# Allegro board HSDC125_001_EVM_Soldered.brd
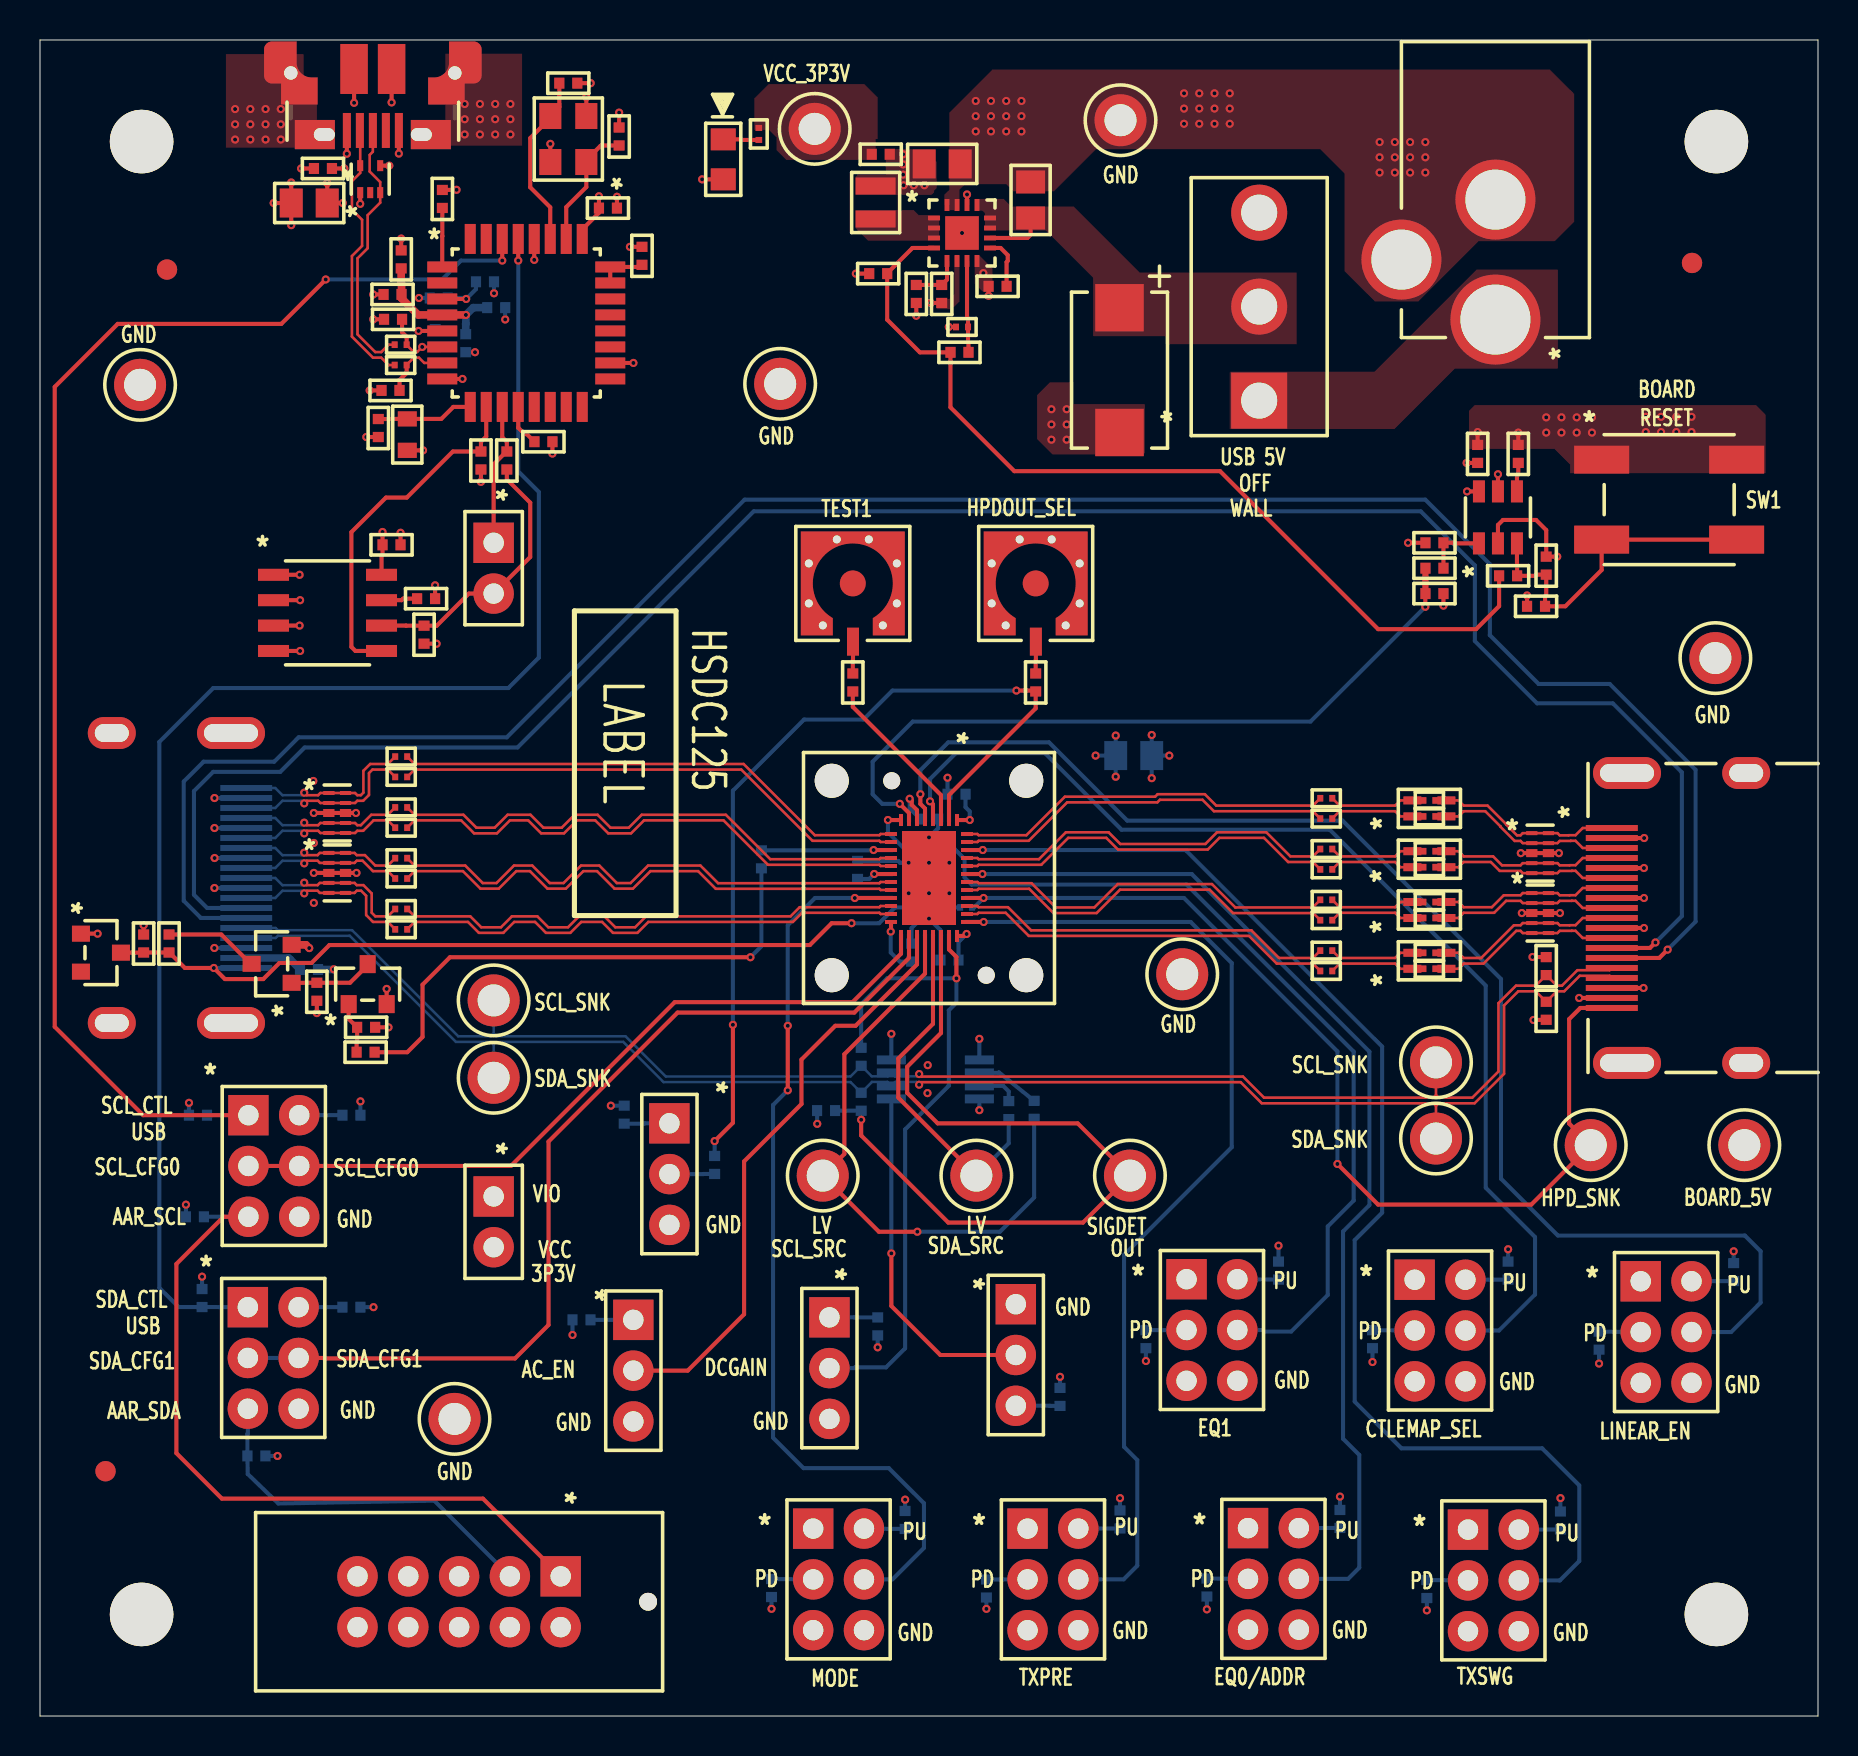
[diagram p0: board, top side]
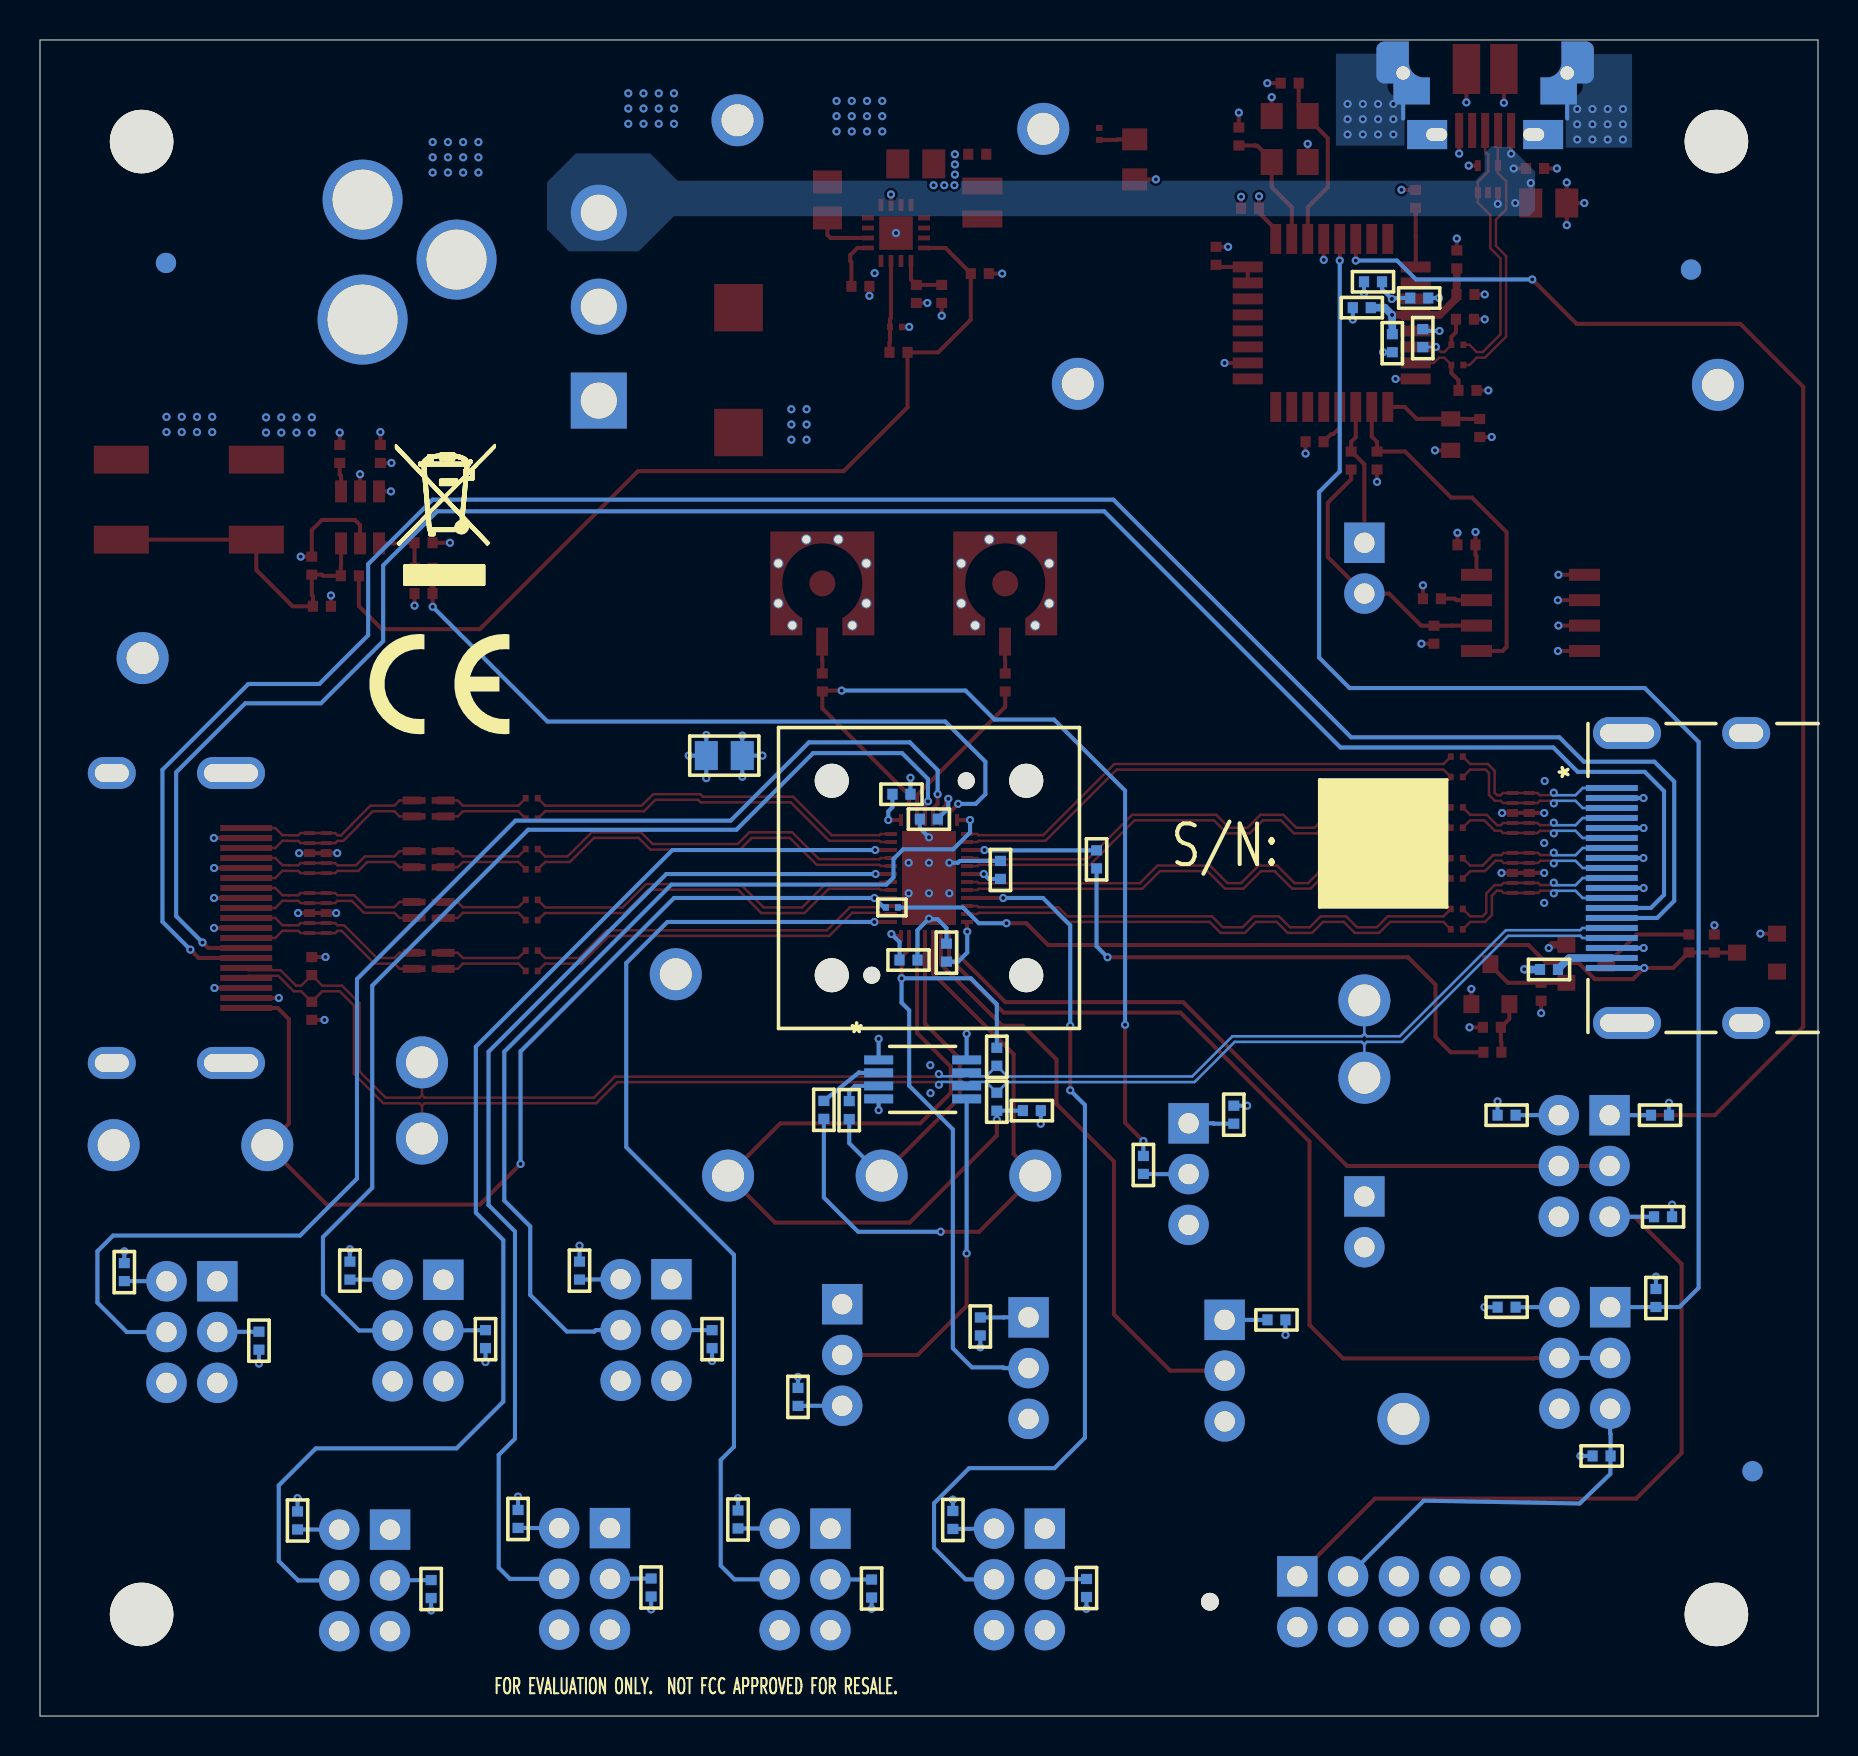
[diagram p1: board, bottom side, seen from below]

Outline 88.9 x 83.82 mm; copper layers: TOP, L2, L3, L4, L5, BOTTOM. Coordinates in mm from the lower left corner of the outline.
Outline path: 0,83.82 88.9,83.82 88.9,0 0,0 0,83.82

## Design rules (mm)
constraint set DEFAULT: min track width 0.203
net group DIFFPAIR0: nets N17024118 N17024121
net group DIFFPAIR1: nets N16919318 N16919400
net group DIFFPAIR2: nets IN_D2N IN_D2P
net group DIFFPAIR3: nets IN_D1N IN_D1P
net group DIFFPAIR4: nets IN_D0N IN_D0P
net group DIFFPAIR5: nets IN_CLKN IN_CLKP
net group DIFFPAIR6: nets IN_D2N_R IN_D2P_R
net group DIFFPAIR7: nets IN_D1N_R IN_D1P_R
net group DIFFPAIR8: nets IN_D0N_R IN_D0P_R
net group DIFFPAIR9: nets IN_CLKN_R IN_CLKP_R
net group DIFFPAIR10: nets OUT_D2N OUT_D2P
net group DIFFPAIR11: nets OUT_D1N OUT_D1P
net group DIFFPAIR12: nets OUT_D0N OUT_D0P
net group DIFFPAIR13: nets OUT_CLKN OUT_CLKP
net group DIFFPAIR14: nets N17100724 N17100737
net group DIFFPAIR15: nets N17100678 N17100691
net group DIFFPAIR16: nets N17100618 N17100645
net group DIFFPAIR17: nets N17100772 N17100781
net group DIFFPAIR18: nets OUTD2N_C OUTD2P_C
net group DIFFPAIR19: nets OUTD1N_C OUTD1P_C
net group DIFFPAIR20: nets OUTD0N_C OUTD0P_C
net group DIFFPAIR21: nets OUTCLKN_C OUTCLKP_C
net group DIFFPAIR22: nets SCL_SNK SDA_SNK
net group DIFF_PAIR 100 OHM_PH: nets EN SCL_CFG0 SCL_CTL_USB SDA_CFG1 SDA_CTL_USB

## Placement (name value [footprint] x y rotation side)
C17  10uF  [CAP_0805]  54.69 48.03 180 bottom
C20  0.1uF  [CAP_0402]  45.47 37.81 180 bottom
C21  0.1uF  [CAP_0402]  44.46 44.85 0 bottom
C22  0.1uF  [CAP_0402]  45.83 46.1 180 bottom
C23  0.1uF  [CAP_0402]  43.58 38.18 90 bottom
C26  DNI - 200nF  [CAP_0402]  69.72 56.13 0 top
C27  18pF  [CAP_0402]  75.31 57.53 90 top
C28  220pF  [CAP_0402]  73.91 63.12 90 top
C29  0.1uF  [CAP_0402]  71.88 63.12 90 top
C30  220uF  [TANT_7343-31]  53.98 67.31 270 top
C31  10uF  [CAP_0805]  49.53 75.82 90 top
C32  22uF  [CAP_0805]  45.11 77.62 0 top
C34  3.3nF  [CAP_0402]  47.88 71.5 180 top
C39  2.2uF  [CAP_0805]  13.46 75.67 180 top
C40  0.1uF  [CAP_0402]  28.4 75.41 180 top
C41  0.01uF  [CAP_0402]  22.25 71.73 180 bottom
C42  0.01uF  [CAP_0402]  19.94 70.92 0 bottom
C45  22pF  [CAP_0402]  17.65 69.85 180 top
C46  0.1uF  [CAP_0402]  21.29 68.66 90 bottom
C47  0.01uF  [CAP_0402]  22.81 70.43 180 bottom
C49  22pF  [CAP_0402]  17.53 66.29 0 top
C50  33pF  [CAP_0402]  28.96 78.99 90 top
C51  33pF  [CAP_0402]  26.42 81.66 0 top
C52  1uF  [CAP_0603]  18.36 64.08 90 top
C59  0.1uF  [CAP_0402]  17.58 58.57 180 top
C60  0.1uF  [CAP_0402]  14.15 77.39 180 top
C61  0.1uF  [CAP_0402]  40.64 51.69 270 top
C63  0.01uF  [CAP_0402]  40.88 42.31 90 bottom
C64  0.1uF  [CAP_0402]  49.78 51.69 270 top
D1  LED Green 0805  [LED_SM_LTST-C171]  34.16 77.85 270 top
D2  Zener 6V  [SOT-23_123]  3.05 38.18 270 top
J5  Header 5x2 0.1" thru-hole  [CON_SHRD_THVT_N2510-6002-XX]  20.95 5.71 270 top
J9  2.1mm x 5.5mm  [JACK_THRT_PJ-202AH]  72.77 69.84 90 top
J13  USB Micro B  [USB-UB_SMRT_10103592]  16.64 81.75 180 top
J18  SMP  [CON_SMVT_19S101-40ML5_R04350]  40.64 56.64 0 top
J25  HDR3X1 M .1  [HDR_THVT_1X3_254_1097]  31.47 27.1 270 top
J27  HDR3X1 M .1  [HDR_THVT_1X3_254_1097]  29.67 17.27 270 top
J30  SMP  [CON_SMVT_19S101-40ML5_R04350]  49.78 56.64 0 top
J31  HDR3X1 M .1  [HDR_THVT_1X3_254_1097]  48.79 18.05 270 top
J32  HEADER 2  [HDR_THVT_1X2_254_820]  22.68 25.98 270 top
J33  HDR3X1 M .1  [HDR_THVT_1X3_254_1097]  39.47 17.4 270 top
JMP4  HEADER 3X2  [HDR_THVT_2X3_254_1097]  38.66 9.37 0 top
JMP5  HEADER 3X2  [HDR_THVT_2X3_254_1097]  68.73 21.82 0 top
JMP6  HEADER 3X2  [HDR_THVT_2X3_254_1097]  57.33 21.84 0 top
JMP7  HEADER 3X2  [HDR_THVT_2X3_254_1097]  49.38 9.37 0 top
JMP8  HEADER 3X2  [HDR_THVT_2X3_254_1097]  60.4 9.4 0 top
JMP9  HEADER 3X2  [HDR_THVT_2X3_254_1097]  71.4 9.32 0 top
JMP13  HEADER 3X2  [HDR_THVT_2X3_254_1097]  80.04 21.74 0 top
JMP15  HEADER 3X2  [HDR_THVT_2X3_254_1097]  10.42 30.05 0 top
JMP16  HEADER 3X2  [HDR_THVT_2X3_254_1097]  10.39 20.45 0 top
JP1  JUMPER  [HDR_THVT_1X2_254_820]  22.68 58.67 270 top
L1  2.2 uH  [IND_SM_VLS252010]  41.78 75.69 90 top
L3  DLM0QSB120HY2B  [IND_SM_4_DLW21S_H]  69.47 42.85 90 top
L4  DLM0QSB120HY2B  [IND_SM_4_DLW21S_H]  69.47 45.39 90 top
L5  DLM0QSB120HY2B  [IND_SM_4_DLW21S_H]  69.47 37.77 90 top
L7  DLM0QSB120HY2B  [IND_SM_4_DLW21S_H]  69.47 40.31 90 top
NOREF  -  [unnamed]  5.08 5.08 0 top
NOREF#2  -  [unnamed]  82.6 72.67 0 top
NOREF#3  -  [unnamed]  6.35 72.34 0 top
NOREF#4  -  [#2]  0 0 0 top
NOREF#5  -  [unnamed]  83.82 5.08 0 top
NOREF#6  -  [#2]  56.16 48.51 0 top
NOREF#7  -  [unnamed]  5.08 78.74 0 top
NOREF#8  -  [#2]  67.03 2.08 0 top
NOREF#9  -  [unnamed]  3.28 12.24 0 top
NOREF#10  -  [unnamed]  83.82 78.74 0 top
NOREF#11  -  [#2]  -3.81 -69.85 0 top
NOREF#12  -  [#2]  88.9 38.1 0 top
NOREF#13  -  [#2]  68.93 51.61 180 bottom
NOREF#14  -  [unnamed]  6.35 72.34 180 bottom
NOREF#15  -  [#2]  68.62 60.6 180 bottom
NOREF#16  -  [#2]  68.34 41.07 180 bottom
NOREF#17  -  [unnamed]  82.6 72.67 180 bottom
NOREF#18  -  [unnamed]  3.28 12.24 180 bottom
NOREF#19  -  [#2]  31.9 43.64 180 bottom
P1  HDMI_IN  [HDMI_SMRT_47151-001]  9.55 41.91 90 bottom
P2  HDMI_OUT  [HDMI_SMRT_47151-001]  79.35 39.91 90 top
Q1  FDV301N_NFET_8V  [SOT-23_123]  16.38 36.6 0 top
Q2  FDV301N_NFET_8V  [SOT-23_123]  11.58 37.62 90 top
R5  100  [RES_0402]  16.28 33.2 180 top
R10  1K  [RES_0402]  5.18 38.63 90 top
R11  1K  [RES_0402]  13.84 36.22 270 top
R12  100K  [RES_0402]  16.31 34.44 180 top
R13  10  [RES_0402]  6.45 38.63 270 top
R27  20K  [RES_0402]  36.58 6.4 270 bottom
R45  DNI  [RES_0402]  75.31 37.5 90 top
R46  DNI  [RES_0402]  75.31 35.27 90 top
R58  2K  [RES_0402]  7.9 30.05 0 bottom
R59  2K  [RES_0402]  8.1 20.9 270 bottom
R77  0  [RES_0402]  69.72 57.4 0 top
R78  10K  [RES_0402]  69.72 58.67 0 top
R79  4.7K  [RES_0402]  74.8 55.5 0 top
R80  0  [RES_0402]  73.41 57.02 180 top
R81  100K  [RES_0402]  41.91 72.14 0 top
R82  499  [RES_0201]  35.94 79.12 90 top
R83  0  [RES_0402]  45.97 68.2 180 top
R84  0  [RES_0402]  42.04 78.11 0 top
R85  750K  [RES_0402]  43.81 71.12 270 top
R86  240K  [RES_0402]  45.09 71.12 90 top
R92  90.9K - DNI  [RES_0402]  18.06 72.85 90 top
R93  100K - DNI  [RES_0402]  17.63 71.09 0 top
R94  1.5K  [RES_0402]  19.76 68.91 270 bottom
R95  33  [RES_0201]  18.03 67.56 180 top
R96  33  [RES_0201]  18.03 68.58 180 top
R98  10K  [RES_0402]  30.1 73.03 270 top
R99  1K  [RES_0402]  22.05 62.79 90 top
R100  1K  [RES_0402]  19.2 54.08 90 top
R101  1K  [RES_0402]  20.12 75.87 90 top
R102  10K  [RES_0402]  25.17 63.73 180 top
R103  15K  [RES_0402]  16.92 64.41 90 top
R104  0  [RES_0402]  13.45 37.33 180 bottom
R120  0 - DNI  [RES_0201]  46.1 69.47 180 top
R121  1K  [RES_0402]  19.3 55.88 0 top
R122  0  [RES_0402]  23.34 62.79 270 top
R129  0 - DNI  [RES_0201]  46.3 40.44 180 bottom
R131  0  [RES_0402]  36.07 42.84 270 bottom
R132  1K  [RES_0402]  43.26 9.8 90 bottom
R133  1K  [RES_0402]  73.41 22.28 90 bottom
R134  20K  [RES_0402]  66.62 18.85 270 bottom
R135  1K  [RES_0402]  61.93 22.28 90 bottom
R136  20K  [RES_0402]  55.3 18.85 270 bottom
R137  1K  [RES_0402]  54 9.83 90 bottom
R138  20K  [RES_0402]  47.32 6.38 270 bottom
R139  1K  [RES_0402]  65 9.86 90 bottom
R140  20K  [RES_0402]  58.34 6.43 270 bottom
R141  1K  [RES_0402]  76.02 9.78 90 bottom
R142  20K  [RES_0402]  69.34 6.35 270 bottom
R150  1K  [RES_0402]  29.21 30.07 90 bottom
R152  1K  [RES_0402]  27.08 19.81 180 bottom
R154  1K  [RES_0402]  84.68 22.2 90 bottom
R155  20K  [RES_0402]  77.95 18.77 270 bottom
R165  0  [RES_0402]  41.06 32.97 270 bottom
R167  0  [RES_0402]  41.06 30.72 90 bottom
R168  0  [RES_0402]  49.71 30.31 90 bottom
R169  0  [RES_0402]  48.44 30.3 90 bottom
R170  10K  [RES_0402]  51 15.96 270 bottom
R171  DNI  [RES_0201]  69.47 40.71 0 top
R172  DNI  [RES_0201]  69.47 39.91 0 top
R173  DNI  [RES_0201]  69.47 43.25 0 top
R174  DNI  [RES_0201]  69.47 42.45 0 top
R175  DNI  [RES_0201]  69.47 45.79 0 top
R176  DNI  [RES_0201]  69.47 44.99 0 top
R177  DNI  [RES_0201]  69.47 38.17 0 top
R178  DNI  [RES_0201]  69.47 37.37 0 top
R180  1K  [RES_0402]  15.57 20.45 0 bottom
R182  0  [RES_0402]  33.73 27.56 90 bottom
R183  0  [RES_0201]  64.31 40.82 0 top
R184  0  [RES_0201]  64.31 39.8 0 top
R185  0  [RES_0201]  64.31 43.36 0 top
R186  0  [RES_0201]  64.31 42.34 0 top
R187  0  [RES_0201]  64.31 45.9 0 top
R188  0  [RES_0201]  64.31 44.88 0 top
R189  0  [RES_0201]  64.31 38.28 0 top
R190  0  [RES_0201]  64.31 37.26 0 top
R191  10K  [RES_0402]  39.31 30.28 0 bottom
R194  1K  [RES_0402]  41.88 19.48 270 bottom
R196  0  [RES_0201]  18.06 47.98 0 top
R197  0  [RES_0201]  18.06 46.96 0 top
R198  0  [RES_0201]  18.06 45.44 0 top
R199  0  [RES_0201]  18.06 44.42 0 top
R200  0  [RES_0201]  18.06 42.9 0 top
R201  0  [RES_0201]  18.06 41.88 0 top
R202  0  [RES_0201]  18.06 40.36 0 top
R203  0  [RES_0201]  18.06 39.34 0 top
R204  1K  [RES_0402]  15.57 30.05 0 bottom
R205  2K  [RES_0402]  7.75 24.97 0 bottom
R206  2K  [RES_0402]  10.82 13 180 bottom
SW1  PB_SWITCH  [SW_SMVT_B3SN-3012]  81.46 60.83 0 top
SW2  3POS - SPDT  [SW_SMVT_MS13ANX03]  60.96 70.48 90 top
TP5  LP  [TP_THVT_5006]  38.73 79.38 180 top
TP8  LP  [TP_THVT_5006]  54.03 79.81 0 top
TP9  LP  [TP_THVT_5006]  37.01 66.62 0 top
TP10  LP  [TP_THVT_5006]  69.8 32.69 0 top
TP11  LP  [TP_THVT_5006]  69.8 28.88 0 top
TP12  LP  [TP_THVT_5006]  85.22 28.55 0 top
TP13  LP  [TP_THVT_5006]  77.54 28.55 0 top
TP14  LP  [TP_THVT_5006]  83.77 52.91 0 top
TP15  LP  [TP_THVT_5006]  22.68 35.79 0 top
TP16  LP  [TP_THVT_5006]  22.68 31.92 0 top
TP17  LP  [TP_THVT_5006]  5 66.57 0 top
TP19  LP  [TP_THVT_5006]  20.73 14.86 0 top
TP20  LP  [TP_THVT_5006]  54.5 27.03 0 top
TP21  LP  [TP_THVT_5006]  57.11 37.1 0 top
TP22  LP  [TP_THVT_5006]  39.14 27.03 0 top
TP23  LP  [TP_THVT_5006]  46.82 27.03 0 top
U1  TDP1204  [SKT_IRONWOOD_C14861_SLDR]  44.45 41.91 270 top
U3  TPS3808  [DBV0006AA]  72.9 59.94 90 top
U4  TPS62150A  [RGT0016EA_168X168]  46.1 74.17 0 top
U7  TUSB3410  [VF0032AA]  24.31 69.67 0 top
U8  CAT24C256WI-GT3  [SOIC_8_390X490_127]  14.38 55.17 0 top
U16  TPD2E001  [DRL0005AA]  16.51 76.86 90 top
U19  TPD4E02B04  [DQA0010BA]  14.86 45.16 0 top
U20  TPD4E02B04  [DQA0010BA]  14.86 42.16 0 top
U21  TPD4E02B04  [DQA0010BA]  75.01 40.16 0 top
U22  TPD4E02B04  [DQA0010BA]  75.01 43.15 0 top
U23  TCA9509  [DGK0008AA]  44.77 31.84 180 bottom
Y1  12 MHz  [XTAL_SM_4_ECX-32]  26.42 78.87 180 top

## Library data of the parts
C17 C20-C23 C26-C29 C31 C32 C34 C39-C42 C45-C47 C49-C52 C59-C61 C63 C64 = CAP NP
C30 = CAPACITOR POL
D1 = DIODE
D2 = Zener 6V
J5 = CONN PCB 5x2-S
J9 = BNC_2
J13 = USB Mini AB_1
J18 J30 = SMP_0
J25 J27 J31 J33 = HDR3X1 M _2.1
J32 = HEADER 2
JMP4-JMP9 JMP13 JMP15 JMP16 = HEADER 3X2
JP1 = JUMPER
L1 = INDUCTOR
L3-L5 L7 = CHOKE CM_0
P1 P2 = CONN HDMI TYPE A
Q1 Q2 = FDV301N_NFET_8V
R5 R10-R13 R27 R132-R142 R150 R152 R154 R155 R180 R182 R194 R204 = r0402
R45 R46 R77-R81 R83-R86 R92-R96 R98-R104 R120-R122 R129 R131 R165 R167-R178 R183-R191 R196-R203 = R
R58 R59 R82 R205 R206 = R_4
SW1 = PB_SWITCH_0
SW2 = SW_SLIDE_SPDT2
TP5 TP8-TP17 TP19-TP23 = TESTLOOP
U1 = TUSB1044RNQ_3
U3 = TPS3808DBV
U4 = TPS62150A_2
U7 = TUSB3410_3
U8 = I2C_0
U16 = TPD2E001-Q1
U19-U22 = ESD224
U23 = TCA9509
Y1 = CRYSTAL14_0

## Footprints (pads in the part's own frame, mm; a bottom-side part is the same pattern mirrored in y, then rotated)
CAP_0402
  rect 0.51x0.55 smd: 1(-0.45,0) 2(0.45,0)
CAP_0603
  rect 0.76x0.95 smd: 1(-0.787,0) 2(0.787,0)
CAP_0805
  rect 1.15x1.45 smd: 1(-0.9,0) 2(0.9,0)
CON_SHRD_THVT_N2510-6002-XX
  round 0.89 hole 0.89 unplated: (0,9.45)
  rect 2.02x2.02 hole 1.02: 1(-1.27,5.08)
  round 2.02 hole 1.02: 2(1.27,5.08) 3(-1.27,2.54) 4(1.27,2.54) 5(-1.27,0) 6(1.27,0) 7(-1.27,-2.54) 8(1.27,-2.54) 9(-1.27,-5.08) 10(1.27,-5.08)
CON_SMVT_19S101-40ML5_R04350
  rect 0.6x1.4 smd: 1(0.01,-2.911)
  custom 1.3x1.3 smd: 2(0,0)
  round 0.508 hole 0.4: 3(0.8,2.2) 4(-0.8,2.2) 5(-2.2,1) 6(-2.2,-1) 7(-1.5,-2.1) 8(1.5,-2.1) 9(2.2,-1) 10(2.2,1)
DBV0006AA
  rect 1.1x0.6 smd: 1(-1.3,0.95) 2(-1.3,0) 3(-1.3,-0.95) 4(1.3,-0.95) 5(1.3,0) 6(1.3,0.95)
DGK0008AA
  rect 1.45x0.45 smd: 1(-2.2,0.975) 2(-2.2,0.325) 3(-2.2,-0.325) 4(-2.2,-0.975) 5(2.2,-0.975) 6(2.2,-0.325) 7(2.2,0.325) 8(2.2,0.975)
DQA0010BA
  rect 0.56x0.2 smd: 1(-0.418,1) 2(-0.418,0.5) 4(-0.418,-0.5) 5(-0.418,-1) 6(0.418,-1) 7(0.418,-0.5) 9(0.418,0.5) 10(0.418,1)
  rect 0.56x0.4 smd: 3(-0.418,0) 8(0.418,0)
DRL0005AA
  rect 0.55x0.3 smd: 1(-0.675,0.5) 2(-0.675,0) 3(-0.675,-0.5) 4(0.675,-0.5) 5(0.675,0.5)
HDMI_SMRT_47151-001
  rect 0.3x2.6 smd: 1(4.5,0.76) 2(4,0.76) 3(3.5,0.76) 4(3,0.76) 5(2.5,0.76) 6(2,0.76) 7(1.5,0.76) 8(1,0.76) 9(0.5,0.76) 10(0,0.76) 11(-0.5,0.76) 12(-1,0.76) 13(-1.5,0.76) 14(-2,0.76) 15(-2.5,0.76) 16(-3,0.76) 17(-3.5,0.76) 18(-4,0.76) 19(-4.5,0.76)
  oval 1.6x3.4 hole 0.9x2.7: 20(-7.25,0) 21(7.25,0)
  oval 1.6x2.4 hole 0.9x1.7: 22(7.25,-5.96) 23(-7.25,-5.96)
HDR_THVT_1X2_254_820
  rect 2.02x2.02 hole 1.02: 1(0,0)
  round 2.02 hole 1.02: 2(2.54,0)
HDR_THVT_1X3_254_1097
  rect 2.02x2.02 hole 1.02: 1(-2.54,0)
  round 2.02 hole 1.02: 2(0,0) 3(2.54,0)
HDR_THVT_2X3_254_1097
  rect 2.02x2.02 hole 1.02: 1(0,0)
  round 2.02 hole 1.02: 2(2.54,0) 3(0,-2.54) 4(2.54,-2.54) 5(0,-5.08) 6(2.54,-5.08)
IND_SM_4_DLW21S_H
  rect 0.4x0.9 smd: 1(-0.4,0.85) 2(-0.4,-0.85) 3(0.4,-0.85) 4(0.4,0.85)
IND_SM_VLS252010
  rect 0.85x2 smd: 1(-0.825,0) 2(0.825,0)
JACK_THRT_PJ-202AH
  round 4.5 hole 3.5: 1(0,0)
  round 4 hole 3: 2(6,0) 3(3,4.7)
LED_SM_LTST-C171
  rect 1.1x1.25 smd: 1(-1,0) 2(1,0)
RES_0201
  rect 0.3x0.33 smd: 1(-0.3,0) 2(0.3,0)
RES_0402
  rect 0.51x0.55 smd: 1(-0.45,0) 2(0.45,0)
RGT0016EA_168X168
  rect 0.6x0.24 smd: 1(-1.4,0.75) 2(-1.4,0.25) 3(-1.4,-0.25) 4(-1.4,-0.75) 9(1.4,-0.75) 10(1.4,-0.25) 11(1.4,0.25) 12(1.4,0.75)
  rect 0.24x0.6 smd: 5(-0.75,-1.4) 6(-0.25,-1.4) 7(0.25,-1.4) 8(0.75,-1.4) 13(0.75,1.4) 14(0.25,1.4) 15(-0.25,1.4) 16(-0.75,1.4)
  rect 1.68x1.68 smd: 17(0,0)
SKT_IRONWOOD_C14861_SLDR
  round 1.7 hole 1.7 unplated: (-4.863,4.863) (-4.863,-4.863) (4.863,4.863) (4.863,-4.863)
  round 0.85 hole 0.85 unplated: (-4.863,-1.863) (4.863,2.863)
  rect 0.6x0.2 smd: 1(-2.9,1.4) 2(-2.9,1) 3(-2.9,0.6) 4(-2.9,0.2) 5(-2.9,-0.2) 6(-2.9,-0.6) 7(-2.9,-1) 8(-2.9,-1.4) 21(2.9,-1.4) 22(2.9,-1) 23(2.9,-0.6) 24(2.9,-0.2) 25(2.9,0.2) 26(2.9,0.6) 27(2.9,1) 28(2.9,1.4)
  rect 0.2x0.6 smd: 9(-2.2,-1.9) 10(-1.8,-1.9) 11(-1.4,-1.9) 12(-1,-1.9) 13(-0.6,-1.9) 14(-0.2,-1.9) 15(0.2,-1.9) 16(0.6,-1.9) 17(1,-1.9) 18(1.4,-1.9) 19(1.8,-1.9) 20(2.2,-1.9) 29(2.2,1.9) 30(1.8,1.9) 31(1.4,1.9) 32(1,1.9) 33(0.6,1.9) 34(0.2,1.9) 35(-0.2,1.9) 36(-0.6,1.9) 37(-1,1.9) 38(-1.4,1.9) 39(-1.8,1.9) 40(-2.2,1.9)
  rect 4.7x2.7 smd: 41(0,0)
SOIC_8_390X490_127
  rect 1.55x0.6 smd: 1(-2.7,1.905) 2(-2.7,0.635) 3(-2.7,-0.635) 4(-2.7,-1.905) 5(2.7,-1.905) 6(2.7,-0.635) 7(2.7,0.635) 8(2.7,1.905)
SOT-23_123
  rect 0.8x0.9 smd: 1(-0.95,-1) 2(0.95,-1) 3(0,1)
SW_SMVT_B3SN-3012
  rect 2.75x1.4 smd: 1(-3.375,2) 2(3.375,2) 3(-3.375,-2) 4(3.375,-2)
SW_SMVT_MS13ANX03
  rect 2.8x2.8 hole 1.8: 1(-4.7,0)
  round 2.8 hole 1.8: 2(0,0) 3(4.7,0)
TANT_7343-31
  rect 2.37x2.43 smd: 1(-3.12,0) 2(3.12,0)
TP_THVT_5006
  round 2.6 hole 1.6: 1(0,0)
unnamed
  round 3.175 hole 3.175 unplated: (0,0)
USB-UB_SMRT_10103592
  rect 0.4x1.75 smd: 1(1.3,2.455) 2(0.65,2.455) 3(0,2.455) 4(-0.65,2.455) 5(-1.3,2.455)
  rect 2x1.46 hole 1.05x0.65: 6(2.425,2.66) 11(-2.425,2.66)
  custom 0.669x0.669 hole 0.7x1.3: 7(4.1,-0.42) 10(-4.1,-0.42)
  rect 1.375x2.5 smd: 8(0.938,-0.62) 9(-0.938,-0.62)
VF0032AA
  rect 1.5x0.55 smd: 1(-4.2,2.8) 2(-4.2,2) 3(-4.2,1.2) 4(-4.2,0.4) 5(-4.2,-0.4) 6(-4.2,-1.2) 7(-4.2,-2) 8(-4.2,-2.8) 17(4.2,-2.8) 18(4.2,-2) 19(4.2,-1.2) 20(4.2,-0.4) 21(4.2,0.4) 22(4.2,1.2) 23(4.2,2) 24(4.2,2.8)
  rect 0.55x1.5 smd: 9(-2.8,-4.2) 10(-2,-4.2) 11(-1.2,-4.2) 12(-0.4,-4.2) 13(0.4,-4.2) 14(1.2,-4.2) 15(2,-4.2) 16(2.8,-4.2) 25(2.8,4.2) 26(2,4.2) 27(1.2,4.2) 28(0.4,4.2) 29(-0.4,4.2) 30(-1.2,4.2) 31(-2,4.2) 32(-2.8,4.2)
XTAL_SM_4_ECX-32
  rect 1.1x1.3 smd: 1(-0.9,1.15) 2(-0.9,-1.15) 3(0.9,-1.15) 4(0.9,1.15)

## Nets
+1V8: C46.2 C47.2 R92.1 R93.2 U7.4
GND: C17.2 C20.2 C21.2 C22.2 C23.2 C26.2 C27.2 C28.2 C29.2 C30.2 C31.2 C32.2 C34.2 C39.2 C40.1 C41.1 C42.1 C45.2 C46.1 C47.1 C49.1 C50.2 C51.2 C52.1 C59.1 C60.2 C63.2 D1.2(K) D2.1 J5.2 J5.10 J9.2 J9.3 J13.5 J13.6 J13.7 J13.8 J13.9 J13.10 J13.11 J18.2 J18.3 J18.4 J18.5 J18.6 J18.7 J18.8 J18.9 J18.10 J25.3 J27.3 J30.2 J30.3 J30.4 J30.5 J30.6 J30.7 J30.8 J30.9 J30.10 J31.1 J33.3 JMP4.6 JMP5.6 JMP6.6 JMP7.6 JMP8.6 JMP9.6 JMP13.6 JMP15.6 JMP16.6 P1.2 P1.5 P1.8 P1.11 P1.17 P1.20 P1.21 P1.22 P1.23(CASE4) P2.2 P2.5 P2.8 P2.11 P2.17 P2.20 P2.21 P2.22 P2.23(CASE4) Q1.2(S) Q2.2(S) R12.1 R27.2 R86.1 R93.1 R101.2 R120.2 R121.2 R134.2 R136.2 R138.2 R140.2 R142.2 R155.2 SW1.1 SW1.2 TP8.1 TP9.1 TP14.1 TP17.1 TP19.1 TP21.1 U1.41 U3.2 U4.6 U4.8 U4.15 U4.16 U4.17 U7.8 U7.18 U7.28 U8.1 U8.2 U8.3 U8.4 U16.4 U19.3 U19.8 U20.3 U20.8 U21.3 U21.8 U22.3 U22.8 U23.4 Y1.2 Y1.4
VCC_3P3V: C17.1 C20.1 C21.1 C22.1 C23.1 C29.1 J32.2 R82.2 R84.1 R132.2 R133.2 R135.2 R137.2 R139.2 R141.2 R154.2 R191.1 R194.2 TP5.1 U1.1 U1.6 U1.20 U1.28 U3.5 U3.6(VDD)
AARDVARK_SCL: J5.1 JMP15.5 R205.2
AARDVARK_SDA: J5.3 JMP16.5 R206.2
AC_EN: J27.2 U1.23
BOARD_3P3V: C32.1 C40.2 C41.2 C42.2 C59.2 L1.2 R79.1 R81.1 R84.2 R85.2 R92.2 R98.1 R99.1 R100.1 R102.1 R103.1 U4.14(VOS) U7.3 U7.25 U8.8
BOARD_5V: P2.18 R10.2 R11.2 R45.2 R46.1 R104.1 TP12.1 U23.8(VCCB)
BOARD_IN: C30.1 C31.1 SW2.2 U4.10 U4.11 U4.12 U4.13
CTLEMAP_SEL: JMP5.4 U1.4
DCGAIN: J33.2 R165.1 U1.27
EN: C26.1 R77.1 U1.7
EQ0/ADDR: JMP8.4 U1.35
EQ1: JMP6.4 U1.8
FB_3PT3V: R85.1 R86.2 U4.5
HDMI_CEC_SNK: P1.13 P2.13
HDMI_IN_5V: P1.18 R104.2
HPD_OUT: R5.1 R131.2
HPD_SNK: P2.19 R129.1 TP13.1 U1.32
HPD_SRC: D2.3 P1.19 R10.1 R13.2 R129.2
HPDOUT_SEL: C64.2 R182.2 U1.2
IN_CLKN: R203.2 U1.19
IN_CLKN_R: P1.12 R203.1 U20.5 U20.6(IO4_S)
IN_CLKP: R202.2 U1.18
IN_CLKP_R: P1.10 R202.1 U20.4 U20.7
IN_D0N: R201.2 U1.16
IN_D0N_R: P1.9 R201.1 U20.2 U20.9
IN_D0P: R200.2 U1.15
IN_D0P_R: P1.7 R200.1 U20.1 U20.10
IN_D1N: R199.2 U1.13
IN_D1N_R: P1.6 R199.1 U19.5 U19.6(IO4_S)
IN_D1P: R198.2 U1.12
IN_D1P_R: P1.4 R198.1 U19.4 U19.7
IN_D2N: R197.2 U1.10
IN_D2N_R: P1.3 R197.1 U19.2 U19.9
IN_D2P: R196.2 U1.9
IN_D2P_R: P1.1 R196.1 U19.1 U19.10
LINEAR_EN: JMP13.4 U1.5
LV_SCL_SRC: R168.1 TP22.1 U1.24
LV_SDA_SRC: R169.1 TP23.1 U1.25
MODE: JMP4.4 U1.17
OUT_CLKN: R190.1 U1.30
OUT_CLKP: R189.1 U1.31
OUT_D0N: R184.1 U1.33
OUT_D0P: R183.1 U1.34
OUT_D1N: R186.1 U1.36
OUT_D1P: R185.1 U1.37
OUT_D2N: R188.1 U1.39
OUT_D2P: R187.1 U1.40
OUTCLKN_C: L5.2 P2.12 R178.2 U21.5 U21.6(IO4_S)
OUTCLKP_C: L5.3(4) P2.10 R177.2 U21.4 U21.7
OUTD0N_C: L7.2 P2.9 R172.2 U21.2 U21.9
OUTD0P_C: L7.3(4) P2.7 R171.2 U21.1 U21.10
OUTD1N_C: L3.2 P2.6 R174.2 U22.5 U22.6(IO4_S)
OUTD1P_C: L3.3(4) P2.4 R173.2 U22.4 U22.7
OUTD2N_C: L4.2 P2.3 R176.2 U22.2 U22.9
OUTD2P_C: L4.3(4) P2.1 R175.2 U22.1 U22.10
PB_MANUAL_RESET: C27.1 R79.2 R80.1 SW1.3(B_) SW1.4 U3.3
PWRIN_SW: J9.1(T) SW2.1
REG_PG: R80.2 R81.2 R83.2 U4.4
RSTIN: C52.2 R103.2 U7.9
SCL_CFG0: JMP15.3 JMP15.4 U1.21
SCL_CTL_USB: JMP15.1 R58.2 U7.30
SCL_SNK: P1.15 P2.15 R45.1 R165.2 TP10.1 TP15.1 U23.7
SDA_CFG1: JMP16.3 JMP16.4 U1.22
SDA_CTL_USB: JMP16.1 R59.2 U7.29
SDA_SNK: P1.16 P2.16 R46.2 R167.2 TP11.1 TP16.1 U23.6
SIGDET_OUT: R167.1 R191.2 TP20.1 U1.26
SPDIF_IN: P1.14 P2.14
TEST1: C61.2 U1.3
TPS3808_CT: C28.1 U3.4
TXPRE: JMP7.4 U1.29
TXSWG: JMP9.4 U1.38
USB_5V: C39.1 C60.1 J13.1(VBUS) SW2.3 U16.1(VCC)
VIO: C63.1 J32.1 R58.1 R59.1 R78.1 R150.2 R152.2 R170.1 R180.2 R204.2 R205.1 R206.1 U1.14(VIO) U23.1
X1: C51.1 U7.27 Y1.3
X2: C50.1 U7.26 Y1.1
N16782838: R77.2 R78.2 U3.1
N16887406: R102.2 U7.12(\\W\A\K\E\U\P\)
N16916452: JP1.1 R122.1 U7.11
N16916458: JP1.2 R100.2 R122.2 U8.6
N16916991: R99.2 U7.10 U8.5
N16919313: R94.1 U7.5
N16919318: C45.1 R94.2 R96.1 U7.6
N16919400: C49.2 R95.1 U7.7
N16919998: R101.1 U7.1
N16965307: R83.1 R120.1 U4.7
N16965311: L1.1 U4.1 U4.2 U4.3
N16965335: C34.1 U4.9
N16968702: R98.2 U7.23 U7.24
N16982334: R121.1 U8.7(WP)
N17024118: J13.2 R95.2 U16.5
N17024121: J13.3 R96.2 U16.3
N17075681: R131.1 U1.11
N17076650: C61.1 J18.1
N17077181: JMP4.2 R132.1
N17077214: JMP4.3 R27.1
N17077452: JMP5.2 R133.1
N17077486: JMP5.3 R134.1
N17077740: JMP6.2 R135.1
N17077774: JMP6.3 R136.1
N17078062: JMP7.2 R137.1
N17078096: JMP7.3 R138.1
N17078348: JMP8.2 R139.1
N17078382: JMP8.3 R140.1
N17078649: JMP9.2 R141.1
N17078683: JMP9.3 R142.1
N17082573: J25.1 R150.1
N17083396: J27.1 R152.1
N17083699: JMP13.2 R154.1
N17083743: JMP13.3 R155.1
N17098810: D1.1 R82.1
N17100064: R168.2 U23.2
N17100067: R169.2 U23.3
N17100133: J31.3 R170.2
N17100137: J31.2 U23.5
N17100618: L7.4 R171.1 R183.2
N17100645: L7.1 R172.1 R184.2
N17100678: L3.4 R173.1 R185.2
N17100691: L3.1 R174.1 R186.2
N17100724: L4.4 R175.1 R187.2
N17100737: L4.1 R176.1 R188.2
N17100772: L5.4 R177.1 R189.2
N17100781: L5.1 R178.1 R190.2
N17106321: C64.1 J30.1
N17106522: J25.2 R182.1
N17107170: Q1.1 R5.2 R12.2
N17107194: Q1.3 Q2.1 R11.1
N17107221: Q2.3 R13.1
N17117344: J33.1 R194.1
N17130852: JMP16.2 R180.1
N17130854: JMP15.2 R204.1

Pads without a net: D2 2; J5 4 5 6 7 8 9; J13 4; JMP4 1 5; JMP5 1 5; JMP6 1 5; JMP7 1 5; JMP8 1 5; JMP9 1 5; JMP13 1 5; U7 2 13 14 15 16 17 19 20 21 22 31 32; U16 2

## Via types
v1: diameter 0.406, hole 0.203, TOP to BOTTOM, 274 vias

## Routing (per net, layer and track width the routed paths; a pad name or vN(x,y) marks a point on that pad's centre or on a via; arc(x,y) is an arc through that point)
+1V8: length 7.2
  TOP w0.381: v1(21.29,70.07) U7.4 18.91,70.07 18.08,70.9 R93.2 18.08,71.6 18.06,71.62 R92.1
  BOTTOM w0.381: C47.2 21.66,70.43 v1(21.29,70.07) 21.29,69.64 21.29,69.63 C46.2
GND: length 494.3
  TOP w0.203: Y1.2 v1(27.32,80.96) ; C51.2 v1(27.53,81.66) ; v1(75.86,57.98) C27.2 75.31,59.31 74.8,59.82 73.15,59.82 72.9,59.56 U3.2 ; v1(13.69,45.16) U19.3 U19.8 v1(15.8,45.16) ; U8.2 v1(13,55.8) ; R86.1 v1(44.53,70.67) ; P2.5 v1(80.2,42.41) ; J13.9 v1(17.58,80.7) ; D1.2 v1(33.11,76.85) ; C49.1 v1(16.48,66.29) ; P2.2 v1(80.21,43.91) ; P2.17 v1(80.18,36.41) ; R93.1 v1(16.66,71.09) ; C39.2 v1(12.56,76.69) ; C39.2 v1(12.56,74.56) ; C39.2 v1(11.68,75.67) ; R121.2 v1(19.75,56.55) ; Y1.4 v1(25.52,78.62) ; C59.1 v1(18.03,59.17) ; J13.8 v1(15.7,80.68) ; C26.2 v1(70.17,55.53) ; C29.2 v1(71.88,64.21) ; v1(13.69,42.16) U20.3 U20.8 v1(15.82,42.16) ; C28.2 v1(73.91,64.19) ; v1(74.09,40.16) U21.3 U21.8 v1(76,40.16) ; J13.5 v1(17.94,78.14) ; C45.2 v1(16.66,69.85) ; U8.1 v1(12.98,57.07) ; U8.4 v1(13,53.26) ; C60.2 v1(13.06,77.39) ; U8.3 v1(12.98,54.53) ; U7.28 v1(24.71,72.82) ; R12.1 v1(17.42,34.44) ; C34.2 v1(47.43,71.03) ; C40.1 v1(28.85,75.98) ; U16.4 v1(17.46,77.54) ; U7.18 v1(29.67,67.67) ; Q1.2 v1(17.33,36.36) ; P2.8 v1(80.2,40.91) ; R120.2 v1(45.44,69.47) ; v1(74.04,43.15) U22.3 U22.8 v1(75.95,43.15) ; C50.2 v1(28.96,80.19) ; P2.11 v1(80.2,39.41) ; R101.2 v1(20.83,76.33) ; U7.8 v1(21.12,66.87) ; D2.1 v1(2.88,39.13) ; C52.1 v1(19.15,63.3)
  TOP w0.381: Q2.2 13.3,38.57 v1(13.46,38.41)
  L2 w0.203: TP17.1 6.48,66.57 ; TP17.1 3.53,66.57 ; TP17.1 5,65.1 ; TP17.1 5,68.05 ; J18.7 39.14,54.97 ; J18.7 39.14,54.11 ; J18.7 38.71,54.54 ; J18.7 39.57,54.54 ; J18.8 42.14,54.97 ; J18.8 41.71,54.54 ; J18.8 42.14,54.11 ; J18.8 42.57,54.54 ; 12.96,23.78 JMP15.6 ; JMP15.6 14.15,24.97 ; JMP15.6 11.77,24.97 ; JMP15.6 12.96,26.16 ; J31.1 48.79,21.78 ; J31.1 49.98,20.59 ; J31.1 48.79,19.41 ; J31.1 47.6,20.59 ; J18.9 42.84,56.07 ; J18.9 42.84,55.21 ; J18.9 43.27,55.64 ; J18.9 42.41,55.64 ; P2.23 85.31,33.64 ; P2.23 83.93,32.66 ; P2.23 85.31,31.68 ; P2.23 86.69,32.66 ; J13.6 14.92,79.09 ; J13.6 12.56,79.09 ; J13.6 14.22,78.18 ; J18.4 39.84,59.27 ; J18.4 40.27,58.84 ; J18.4 39.84,58.41 ; J18.4 39.41,58.84 ; 41.44,58.41 J18.3 ; J18.3 41.87,58.84 ; J18.3 41.01,58.84 ; J18.3 41.44,59.27 ; 50.58,58.41 J30.3 ; J30.3 50.15,58.84 ; J30.3 50.58,59.27 ; J30.3 51.02,58.84 ; 51.92,3.1 JMP7.6 ; JMP7.6 50.73,4.29 ; JMP7.6 53.11,4.29 ; JMP7.6 51.92,5.48 ; 2.21,34.66 P1.23 ; P1.23 4.97,34.66 ; P1.23 3.59,35.64 ; P1.23 3.59,33.68 ; 52.55,79.81 TP8.1 ; TP8.1 54.03,78.33 ; TP8.1 55.5,79.81 ; TP8.1 54.03,81.29 ; 85.31,46.18 P2.22 ; P2.22 83.93,47.16 ; P2.22 85.31,48.14 ; P2.22 86.69,47.16 ; J30.5 48.02,57.64 ; J30.5 47.58,58.07 ; J30.5 47.15,57.64 ; J30.5 47.58,57.21 ; J27.3 30.86,14.73 ; J27.3 29.67,13.54 ; J27.3 28.48,14.73 ; J27.3 29.67,15.92 ; J30.8 51.28,54.97 ; J30.8 51.28,54.11 ; J30.8 51.72,54.54 ; J30.8 50.85,54.54 ; J30.4 48.98,59.27 ; J30.4 48.98,58.41 ; J30.4 49.42,58.84 ; J30.4 48.55,58.84 ; 3.59,48.18 P1.22 ; P1.22 3.59,50.14 ; P1.22 4.97,49.16 ; P1.22 2.21,49.16 ; 7.67,49.16 P1.21 ; P1.21 9.55,48.18 ; P1.21 9.55,50.14 ; P1.21 11.43,49.16 ; J30.9 52.42,55.64 ; J30.9 51.55,55.64 ; J30.9 51.98,55.21 ; J30.9 51.98,56.07 ; J33.3 40.66,14.86 ; J33.3 39.47,16.05 ; J33.3 38.28,14.86 ; J33.3 39.47,13.67 ; TP9.1 38.49,66.62 ; TP9.1 37.01,65.15 ; TP9.1 35.53,66.62 ; TP9.1 37.01,68.1 ; P2.21 81.23,47.16 ; P2.21 77.47,47.16 ; P2.21 79.35,46.18 ; P2.21 79.35,48.14 ; J30.7 48.28,54.97 ; J30.7 48.72,54.54 ; J30.7 47.85,54.54 ; J30.7 48.28,54.11 ; 9.55,33.68 P1.20 ; P1.20 7.67,34.66 ; P1.20 9.55,35.64 ; P1.20 11.43,34.66 ; 70.59,75.84 J9.2 ; J9.2 74.95,75.84 ; J9.2 72.77,73.66 ; J9.2 72.77,78.02 ; JMP5.6 72.46,16.74 ; JMP5.6 71.27,17.93 ; JMP5.6 71.27,15.55 ; JMP5.6 70.08,16.74 ; 15.88,4.45 17.06,4.45 ; 15.88,4.45 15.88,3.26 ; 15.88,4.45 14.69,4.45 ; 15.88,4.45 15.88,5.63 ; TP14.1 83.77,54.39 ; TP14.1 85.25,52.91 ; TP14.1 82.29,52.91 ; TP14.1 83.77,51.43 ; 18.36,79.09 J13.11 ; J13.11 19.07,78.18 ; J13.11 20.72,79.09 ; J30.6 47.58,56.07 ; J30.6 48.02,55.64 ; J30.6 47.58,55.21 ; J30.6 47.15,55.64 ; J9.3 68.07,75.02 ; J9.3 68.07,70.66 ; J9.3 65.89,72.84 ; J9.3 70.25,72.84 ; 77.47,32.66 P2.20 ; P2.20 79.35,33.64 ; P2.20 79.35,31.68 ; P2.20 81.23,32.66 ; JMP16.6 14.12,15.37 ; JMP16.6 11.74,15.37 ; JMP16.6 12.93,14.18 ; JMP16.6 12.93,16.56 ; J18.10 42.84,58.07 ; J18.10 42.41,57.64 ; J18.10 42.84,57.21 ; J18.10 43.27,57.64 ; 51.98,57.21 J30.10 ; J30.10 52.42,57.64 ; J30.10 51.98,58.07 ; J30.10 51.55,57.64 ; 38.01,55.64 J18.6 ; J18.6 38.87,55.64 ; J18.6 38.44,56.07 ; J18.6 38.44,55.21 ; 26.04,4.45 26.04,5.63 ; 26.04,4.45 24.85,4.45 ; 26.04,4.45 26.04,3.26 ; 26.04,4.45 27.22,4.45 ; 62.94,3.13 JMP8.6 ; JMP8.6 64.13,4.32 ; JMP8.6 61.75,4.32 ; JMP8.6 62.94,5.51 ; JMP4.6 41.2,5.48 ; JMP4.6 42.39,4.29 ; JMP4.6 40.01,4.29 ; JMP4.6 41.2,3.1 ; 38.44,57.21 J18.5 ; J18.5 38.87,57.64 ; J18.5 38.44,58.07 ; J18.5 38.01,57.64 ; J25.3 31.47,25.75 ; J25.3 32.66,24.56 ; J25.3 30.28,24.56 ; J25.3 31.47,23.37 ; 11.71,82.17 J13.7 12.54,79.89 ; 82.58,15.47 JMP13.6 ; JMP13.6 82.58,17.85 ; JMP13.6 81.39,16.66 ; JMP13.6 83.76,16.66 ; 20.74,79.89 J13.10 21.57,82.17 ; TP19.1 20.73,16.34 ; TP19.1 19.25,14.86 ; TP19.1 22.2,14.86 ; TP19.1 20.73,13.38 ; JMP6.6 61.06,16.76 ; JMP6.6 58.68,16.76 ; JMP6.6 59.87,17.95 ; JMP6.6 59.87,15.58 ; JMP9.6 75.13,4.24 ; JMP9.6 72.75,4.24 ; JMP9.6 73.94,5.43 ; JMP9.6 73.94,3.05
  L5 w0.203: 39.84,58.41 J18.4 ; J18.4 39.41,58.84 ; J18.4 39.84,59.27 ; J18.4 40.27,58.84 ; 26.04,4.45 26.04,5.63 ; 26.04,4.45 24.85,4.45 ; 26.04,4.45 27.22,4.45 ; 26.04,4.45 26.04,3.26 ; JMP13.6 83.76,16.66 ; JMP13.6 81.39,16.66 ; JMP13.6 82.58,15.47 ; JMP13.6 82.58,17.85 ; J25.3 31.47,25.75 ; J25.3 31.47,23.37 ; J25.3 30.28,24.56 ; J25.3 32.66,24.56 ; 3.59,33.68 P1.23 ; P1.23 4.97,34.66 ; P1.23 3.59,35.64 ; P1.23 2.21,34.66 ; TP14.1 83.77,54.39 ; TP14.1 83.77,51.43 ; TP14.1 85.25,52.91 ; TP14.1 82.29,52.91 ; J18.3 41.44,59.27 ; J18.3 41.01,58.84 ; J18.3 41.44,58.41 ; J18.3 41.87,58.84 ; 42.84,57.21 J18.10 ; J18.10 42.84,58.07 ; J18.10 42.41,57.64 ; J18.10 43.27,57.64 ; 79.35,46.18 P2.21 ; P2.21 81.23,47.16 ; P2.21 79.35,48.14 ; P2.21 77.47,47.16 ; JMP8.6 64.13,4.32 ; JMP8.6 62.94,3.13 ; JMP8.6 61.75,4.32 ; JMP8.6 62.94,5.51 ; 51.92,3.1 JMP7.6 ; JMP7.6 50.73,4.29 ; JMP7.6 53.11,4.29 ; JMP7.6 51.92,5.48 ; J13.11 20.72,79.09 ; J13.11 18.36,79.09 ; J13.11 19.07,78.18 ; 58.68,16.76 JMP6.6 ; JMP6.6 61.06,16.76 ; JMP6.6 59.87,15.58 ; JMP6.6 59.87,17.95 ; JMP4.6 42.39,4.29 ; JMP4.6 40.01,4.29 ; JMP4.6 41.2,5.48 ; JMP4.6 41.2,3.1 ; 50.58,58.41 J30.3 ; J30.3 51.02,58.84 ; J30.3 50.15,58.84 ; J30.3 50.58,59.27 ; 12.96,23.78 JMP15.6 ; JMP15.6 12.96,26.16 ; JMP15.6 14.15,24.97 ; JMP15.6 11.77,24.97 ; TP8.1 54.03,81.29 ; TP8.1 55.5,79.81 ; TP8.1 52.55,79.81 ; TP8.1 54.03,78.33 ; 68.07,70.66 J9.3 ; J9.3 70.25,72.84 ; J9.3 68.07,75.02 ; J9.3 65.89,72.84 ; 51.28,54.11 J30.8 ; J30.8 51.28,54.97 ; J30.8 51.72,54.54 ; J30.8 50.85,54.54 ; 51.98,55.21 J30.9 ; J30.9 51.55,55.64 ; J30.9 52.42,55.64 ; J30.9 51.98,56.07 ; J33.3 39.47,16.05 ; J33.3 39.47,13.67 ; J33.3 38.28,14.86 ; J33.3 40.66,14.86 ; 15.88,3.26 15.88,4.45 ; 15.88,4.45 15.88,5.63 ; 15.88,4.45 14.69,4.45 ; 15.88,4.45 17.06,4.45 ; P2.23 86.69,32.66 ; P2.23 85.31,31.68 ; P2.23 85.31,33.64 ; P2.23 83.93,32.66 ; P1.21 11.43,49.16 ; P1.21 7.67,49.16 ; P1.21 9.55,48.18 ; P1.21 9.55,50.14 ; 85.31,46.18 P2.22 ; P2.22 86.69,47.16 ; P2.22 83.93,47.16 ; P2.22 85.31,48.14 ; JMP16.6 14.12,15.37 ; JMP16.6 12.93,14.18 ; JMP16.6 11.74,15.37 ; JMP16.6 12.93,16.56 ; J30.7 48.72,54.54 ; J30.7 48.28,54.11 ; J30.7 48.28,54.97 ; J30.7 47.85,54.54 ; J30.5 48.02,57.64 ; J30.5 47.15,57.64 ; J30.5 47.58,57.21 ; J30.5 47.58,58.07 ; 35.53,66.62 TP9.1 ; TP9.1 38.49,66.62 ; TP9.1 37.01,65.15 ; TP9.1 37.01,68.1 ; 70.08,16.74 JMP5.6 ; JMP5.6 71.27,15.55 ; JMP5.6 71.27,17.93 ; JMP5.6 72.46,16.74 ; 14.22,78.18 J13.6 ; J13.6 14.92,79.09 ; J13.6 12.56,79.09 ; 38.44,55.21 J18.6 ; J18.6 38.01,55.64 ; J18.6 38.87,55.64 ; J18.6 38.44,56.07 ; P1.20 9.55,35.64 ; P1.20 11.43,34.66 ; P1.20 7.67,34.66 ; P1.20 9.55,33.68 ; 79.35,31.68 P2.20 ; P2.20 77.47,32.66 ; P2.20 81.23,32.66 ; P2.20 79.35,33.64 ; J18.9 42.84,56.07 ; J18.9 42.84,55.21 ; J18.9 42.41,55.64 ; J18.9 43.27,55.64 ; 51.98,57.21 J30.10 ; J30.10 52.42,57.64 ; J30.10 51.98,58.07 ; J30.10 51.55,57.64 ; TP17.1 5,68.05 ; TP17.1 3.53,66.57 ; TP17.1 6.48,66.57 ; TP17.1 5,65.1 ; 55.63,37.1 TP21.1 ; TP21.1 58.59,37.1 ; TP21.1 57.11,35.62 ; TP21.1 57.11,38.57 ; 20.73,13.38 TP19.1 ; TP19.1 20.73,16.34 ; TP19.1 22.2,14.86 ; TP19.1 19.25,14.86 ; 47.6,20.59 J31.1 ; J31.1 48.79,21.78 ; J31.1 48.79,19.41 ; J31.1 49.98,20.59 ; J18.7 39.14,54.97 ; J18.7 39.57,54.54 ; J18.7 39.14,54.11 ; J18.7 38.71,54.54 ; JMP9.6 73.94,5.43 ; JMP9.6 73.94,3.05 ; JMP9.6 75.13,4.24 ; JMP9.6 72.75,4.24 ; J18.5 38.87,57.64 ; J18.5 38.44,57.21 ; J18.5 38.01,57.64 ; J18.5 38.44,58.07 ; 28.48,14.73 J27.3 ; J27.3 30.86,14.73 ; J27.3 29.67,13.54 ; J27.3 29.67,15.92 ; 21.57,82.17 J13.10 20.74,79.89 ; J18.8 42.57,54.54 ; J18.8 41.71,54.54 ; J18.8 42.14,54.11 ; J18.8 42.14,54.97 ; 70.59,75.84 J9.2 ; J9.2 74.95,75.84 ; J9.2 72.77,78.02 ; J9.2 72.77,73.66 ; 48.98,58.41 J30.4 ; J30.4 48.98,59.27 ; J30.4 49.42,58.84 ; J30.4 48.55,58.84 ; 12.54,79.89 J13.7 11.71,82.17 ; P1.22 4.97,49.16 ; P1.22 3.59,50.14 ; P1.22 3.59,48.18 ; P1.22 2.21,49.16 ; 47.15,55.64 J30.6 ; J30.6 47.58,56.07 ; J30.6 48.02,55.64 ; J30.6 47.58,55.21
  BOTTOM w0.203: P1.11 v1(8.72,41.41) ; R138.2 v1(47.32,5.36) ; C22.2 v1(45.38,46.92) ; C20.2 45.02,39.3 v1(44.45,39.88) 44.42,39.85 44.02,39.85 43.58,39.41 C23.2 ; C63.2 42.91,42.76 43,42.67 v1(43.43,42.67) ; C17.2 v1(53.79,46.98) ; C17.2 v1(53.79,49.03) ; C17.2 v1(52.78,48.03) ; R136.2 v1(55.3,17.75) ; 11.71,82.17 J13.7 12.54,79.89 ; 21.57,82.17 J13.10 20.74,79.89 ; C47.1 v1(23.26,69.84) ; C42.1 v1(18.95,70.92) ; R140.2 v1(58.34,5.33) ; P1.17 v1(8.72,38.41) ; R155.2 v1(77.95,17.63) ; U23.4 v1(46.97,30.3) ; R27.2 v1(36.58,5.36) ; R134.2 v1(66.62,17.7) ; C21.2 44.91,44.4 v1(44.45,43.94) ; P1.5 v1(8.72,44.41) ; R142.2 v1(69.34,5.28) ; P1.8 v1(8.73,42.91) ; P1.2 v1(8.72,45.91) ; C46.1 v1(21.75,68.21) ; C41.1 v1(22.7,71.15)
  vias: v1(9.75,80.37) v1(9.75,79.6) v1(9.75,78.84) v1(10.52,80.37) v1(10.52,79.6) v1(10.52,78.84) v1(11.28,80.37) v1(11.28,79.6) v1(11.28,78.84) v1(12.04,80.37) v1(12.04,79.6) v1(12.04,78.84) v1(13.67,46.76) v1(13.69,43.66) v1(13.69,40.67) v1(21.23,80.62) v1(21.23,79.86) v1(21.23,79.1) v1(22,80.62) v1(22,79.86) v1(22,79.1) v1(22.76,80.62) v1(22.76,79.86) v1(22.76,79.1) v1(23.52,80.62) v1(23.52,79.86) v1(23.52,79.1) v1(43.43,41.15) v1(44.39,32.55) v1(44.37,31.15) v1(44.45,42.67) v1(44.45,41.15) v1(45.47,42.67) v1(45.47,41.15) v1(46.1,74.17) v1(46.79,80.77) v1(46.79,80.01) v1(46.79,79.25) v1(47.17,72.16) v1(47.55,80.77) v1(47.55,80.01) v1(47.55,79.25) v1(48.31,80.77) v1(48.31,80.01) v1(48.31,79.25) v1(49.07,80.77) v1(49.07,80.01) v1(49.07,79.25) v1(50.57,65.35) v1(50.57,64.59) v1(50.57,63.83) v1(51.33,65.35) v1(51.33,64.59) v1(51.33,63.83) v1(57.2,81.15) v1(57.2,80.39) v1(57.2,79.63) v1(57.96,81.15) v1(57.96,80.39) v1(57.96,79.63) v1(58.72,81.15) v1(58.72,80.39) v1(58.72,79.63) v1(59.49,81.15) v1(59.49,80.39) v1(59.49,79.63) v1(66.98,78.71) v1(66.98,77.95) v1(66.98,77.19) v1(67.74,78.71) v1(67.74,77.95) v1(67.74,77.19) v1(68.5,78.71) v1(68.5,77.95) v1(68.5,77.19) v1(69.27,78.71) v1(69.27,77.95) v1(69.27,77.19) v1(75.31,64.95) v1(75.31,64.19) v1(76.07,64.95) v1(76.07,64.19) v1(76.83,64.95) v1(76.83,64.19) v1(77.6,64.95) v1(77.6,64.19) v1(80.29,64.97) v1(80.29,64.21) v1(81.05,64.97) v1(81.05,64.21) v1(81.81,64.97) v1(81.81,64.21) v1(82.58,64.97) v1(82.58,64.21)
VCC_3P3V: length 24.9
  TOP w0.203: U1.1 v1(46.49,44.81) ; v1(43.48,45.87) 43.59,45.77 43.59,45.57 43.85,45.3 U1.6 43.85,44.71 ; U3.5 v1(72.9,62.1) ; v1(42.54,39.23) 42.55,39.24 U1.20 ; U3.6 v1(71.35,61.24) ; U1.28 46.23,39.01 v1(46.33,39.11) ; C29.1 v1(71.33,62.67)
  L4 w0.203: J32.2 23.87,23.44 ; J32.2 22.68,24.63 ; J32.2 21.49,23.44 ; J32.2 22.68,22.26
  BOTTOM w0.203: R137.2 v1(54,10.9) ; v1(46.33,39.11) 45.92,38.7 C20.1 ; C17.1 v1(55.59,46.9) ; C17.1 v1(55.59,49.06) ; C17.1 v1(56.46,48.03) ; R154.2 v1(84.68,23.24) ; R194.2 v1(41.88,18.44) ; C23.1 42.99,37.73 42.54,38.18 v1(42.54,39.23) ; R133.2 v1(73.41,23.34) ; v1(43.48,45.87) 43.48,45.4 44.01,44.87 C21.1 ; R141.2 v1(76.02,10.9) ; C22.1 46.28,45.45 46.49,45.24 v1(46.49,44.81) ; R191.1 v1(38.86,29.62) ; R135.2 v1(61.93,23.52) ; R132.2 v1(43.26,10.82) ; R139.2 v1(65,10.97)
AARDVARK_SCL: length 38
  TOP w0.203: 26.04,6.99 22.15,10.87 9.09,10.87 6.82,13.14 6.82,22.61 9.18,24.97 JMP15.5
  BOTTOM w0.203: R205.2 JMP15.5
AARDVARK_SDA: length 18.5
  BOTTOM w0.203: 23.5,6.99 19.71,10.77 11.92,10.63 10.39,12.1 R206.2 10.37,14.11 10.39,14.13 JMP16.5
AC_EN: length 29.9
  TOP w0.203: J27.2 32.38,17.27 35.2,20.09 35.2,27.74 38.07,30.61 38.07,32.83 39.76,34.52 40.78,34.52 43.85,37.59 U1.23 43.85,39.11
BOARD_3P3V: length 13.8
  TOP w0.203: R103.1 v1(16.31,63.96) ; R98.1 v1(29.5,73.48) ; R85.2 v1(43.81,70.03) ; R99.1 v1(22.05,61.72) ; R79.1 v1(74.35,56.04) ; U8.8 17.08,58.02 17.13,58.07 C59.2 v1(17.13,59.21) ; U7.3 v1(21.31,70.87) ; R100.1 v1(19.83,53.63) ; U4.14 v1(46.35,76.09) ; R92.2 v1(18.06,73.89) ; R102.1 v1(25.62,63.14) ; R81.1 v1(40.79,72.14) ; v1(27.95,76) C40.2 27.95,75.18 27.11,74.34 U7.25
  BOTTOM w0.203: C41.2 21.8,71.36 v1(21.31,70.87) 21.26,70.92 C42.2
  vias: v1(43.15,78.11) v1(43.15,77.6) v1(43.15,77.09) v1(43.18,76.56) v1(43.69,76.56) v1(44.22,76.56)
BOARD_5V: length 6.1
  TOP w0.203: R10.2 v1(5.18,39.55) ; R11.2 v1(13.84,35.15) ; P2.18 v1(76.96,35.91) ; R46.1 v1(74.68,34.81) ; R45.2 v1(74.63,37.96)
  BOTTOM w0.203: U23.8 v1(42.57,34.12)
  BOTTOM w0.381: v1(14.69,37.35) 14.68,37.33 R104.1
BOARD_IN: length 2.9
  TOP w0.203: U4.10 49.37,73.92 49.53,74.08 C31.1
CTLEMAP_SEL: length 56
  TOP w0.203: v1(44.5,45.75) 44.65,45.6 U1.4 44.65,44.71
  BOTTOM w0.203: JMP5.4 72.95,19.28 74.75,21.08 74.75,23.95 72.29,26.42 72.29,36.53 64.49,44.32 54.08,44.32 50.25,48.15 45.79,48.15 44.5,46.86 v1(44.5,45.75)
DCGAIN: length 33.6
  TOP w0.203: v1(45.82,36.89) 45.82,37.96 45.45,38.33 U1.27 45.45,39.11
  BOTTOM w0.203: J33.2 40.71,17.4 40.75,17.44 42.3,17.44 43.26,18.39 43.26,29.34 45.44,31.52 45.44,35.29 45.82,35.67 v1(45.82,36.89) 42.35,36.89 41.06,35.6 R165.1
EN: length 37.1
  TOP w0.203: v1(69.27,55.47) 69.27,56.13 C26.1 ; v1(42.99,45.62) 43.45,45.16 U1.7 43.45,44.71
  TOP w0.305: C26.1 R77.1
  BOTTOM w0.203: v1(42.99,45.62) 42.11,45.62 41.63,46.1 41.63,47.73 43.64,49.73 63.53,49.73 v1(69.27,55.47)
EQ0/ADDR: length 53.8
  TOP w0.203: v1(47.12,42.11) U1.35 46.25,42.11
  BOTTOM w0.203: JMP8.4 65.41,6.86 65.96,7.42 65.96,13.06 65.15,13.87 65.15,24.23 66.47,25.55 66.47,33.22 57.59,42.11 v1(47.12,42.11)
EQ1: length 47.7
  TOP w0.203: U1.8 v1(42.4,44.81)
  BOTTOM w0.203: JMP6.4 61.11,19.3 61.18,19.23 62.56,19.23 64.39,21.06 64.39,24.49 65.68,25.78 65.68,33.22 57.33,41.58 46.58,41.58 46.23,41.94 46.23,42.86 45.74,43.35 43.24,43.35 42.4,44.19 v1(42.4,44.81)
FB_3PT3V: length 2.6
  TOP w0.203: U4.5 45.35,71.84 R86.2 R85.1
HDMI_CEC_SNK: length 107.2
  TOP w0.203: P2.13 80.5,38.41 v1(80.77,38.68)
  BOTTOM w0.203: P1.13 8.36,40.41 7.7,41.07 7.7,46.25 8.66,47.22 12.01,47.22 13.23,48.44 23.88,48.44 35.69,60.25 69.04,60.25 71.74,57.54 71.74,53.76 74.85,50.65 78.64,50.65 82.09,47.19 82.09,40.01 v1(80.77,38.68)
HDMI_IN_5V: length 2.9
  BOTTOM w0.381: P1.18 12.43,37.91 12.51,37.83 12.52,37.83 13,37.35 R104.2
HPD_OUT: length 27
  TOP w0.203: v1(35.52,37.95) 20.5,37.95 19.13,36.58 19.13,33.96 18.36,33.2 R5.1
  BOTTOM w0.203: v1(35.52,37.95) 36.07,38.5 R131.2
HPD_SNK: length 52
  TOP w0.203: v1(47.18,40.91) U1.32 46.25,40.91 ; v1(64.87,27.61) 66.9,25.58 74.57,25.58 TP13.1 76.46,29.63 76.46,34.85 77.01,35.41 P2.19
  BOTTOM w0.203: R129.1 46.7,40.44 v1(47.18,40.91) 57.2,40.91 64.87,33.24 v1(64.87,27.61)
HPD_SRC: length 45.6
  TOP w0.203: D2.3 5.17,38.18 R10.1 R13.2 6.47,38.18 7.25,37.41 v1(8.69,37.41) 9.25,36.86 11.16,36.86 11.97,37.66 13.57,37.66 14.47,38.56 38.49,38.56 39.59,39.65 v1(40.58,39.65)
  BOTTOM w0.203: P1.19 v1(8.69,37.41) ; R129.2 42.75,40.44 41.96,39.65 v1(40.58,39.65)
HPDOUT_SEL: length 44.2
  TOP w0.203: v1(33.73,28.75) 34.65,29.67 v1(34.65,34.57) ; 45.45,44.71 U1.2 45.45,46.06 49.78,50.39 C64.2 49.74,51.28 v1(48.82,51.28)
  BOTTOM w0.203: v1(34.65,34.57) 34.65,46.28 38.2,49.83 41.17,49.83 42.62,51.28 v1(48.82,51.28) ; R182.2 v1(33.73,28.75)
IN_CLKN: length 26
  TOP w0.127: R203.2 18.73,39.71 21.4,39.71 21.94,39.17 23.16,39.17 23.71,39.71 24.75,39.71 25.3,39.17 26.52,39.17 27.06,39.71 28.1,39.71 28.65,39.17 29.87,39.17 30.42,39.71 37.64,39.71 38.1,40.17 41.97,40.17 42.03,40.11 U1.19 42.65,40.11
IN_CLKN_R: length 9.2
  TOP w0.127: R203.1 17.39,39.71 16.65,39.71 16.31,40.06 16.31,41.02 16.05,41.27 15.84,41.27 15.73,41.16 U20.6 U20.5 13.99,41.16 13.88,41.27 13.34,41.27 v1(13.21,41.14)
  BOTTOM w0.127: P1.12 11.76,40.91 12.12,41.27 13.08,41.27 v1(13.21,41.14)
IN_CLKP: length 26
  TOP w0.127: 42.65,40.51 U1.18 42.03,40.51 41.97,40.45 37.99,40.45 37.53,39.99 30.3,39.99 29.75,39.45 28.77,39.45 28.22,39.99 26.95,39.99 26.4,39.45 25.41,39.45 24.87,39.99 23.59,39.99 23.05,39.45 22.06,39.45 21.51,39.99 18.73,39.99 R202.2
IN_CLKP_R: length 9.2
  TOP w0.127: v1(13.21,41.68) 13.33,41.55 13.88,41.55 13.99,41.66 U20.4 U20.7 15.73,41.66 15.84,41.55 16.17,41.55 16.59,41.14 16.59,40.17 16.77,39.99 17.39,39.99 R202.1
  BOTTOM w0.127: v1(13.21,41.68) 13.08,41.55 12.12,41.55 11.76,41.91 P1.10
IN_D0N: length 27
  TOP w0.127: 42.65,41.31 U1.16 42.03,41.31 41.97,41.37 33.79,41.37 32.91,42.25 30.52,42.25 29.64,41.38 28.73,41.38 27.85,42.25 27.17,42.25 26.29,41.38 25.38,41.38 24.5,42.25 23.81,42.25 22.94,41.38 22.02,41.38 21.15,42.25 18.73,42.25 R201.2
IN_D0N_R: length 8.2
  TOP w0.127: R201.1 17.39,42.25 16.65,42.25 16.13,42.77 15.84,42.77 15.73,42.66 U20.9 U20.2 13.99,42.66 13.88,42.77 13.34,42.77 v1(13.21,42.64)
  BOTTOM w0.127: P1.9 11.76,42.41 12.12,42.77 13.08,42.77 v1(13.21,42.64)
IN_D0P: length 27
  TOP w0.127: R200.2 18.73,42.53 21.26,42.53 22.14,41.66 22.82,41.66 23.7,42.53 24.61,42.53 25.49,41.66 26.18,41.66 27.05,42.53 27.97,42.53 28.84,41.66 29.53,41.66 30.4,42.53 33.02,42.53 33.9,41.65 41.97,41.65 42.03,41.71 U1.15 42.65,41.71
IN_D0P_R: length 8.2
  TOP w0.127: v1(13.21,43.18) 13.33,43.05 13.88,43.05 13.99,43.16 U20.1 U20.10 15.73,43.16 15.84,43.05 16.24,43.05 16.77,42.53 17.39,42.53 R200.1
  BOTTOM w0.127: P1.7 11.76,43.41 12.12,43.05 13.08,43.05 v1(13.21,43.18)
IN_D1N: length 27
  TOP w0.127: 42.65,42.51 U1.13 42.03,42.51 41.97,42.57 36.4,42.57 34.18,44.79 30.2,44.79 29.55,44.15 28.41,44.15 27.76,44.79 26.85,44.79 26.2,44.15 25.06,44.15 24.41,44.79 23.5,44.79 22.85,44.15 21.7,44.15 21.06,44.79 18.73,44.79 R199.2
IN_D1N_R: length 8.2
  TOP w0.127: R199.1 17.39,44.79 16.68,44.79 16.16,44.27 15.86,44.27 15.75,44.16 U19.6 U19.5 14.02,44.16 13.91,44.27 13.34,44.27 v1(13.21,44.14)
  BOTTOM w0.127: v1(13.21,44.14) 13.08,44.27 12.12,44.27 11.76,43.91 P1.6
IN_D1P: length 27
  TOP w0.127: R198.2 18.73,45.07 21.17,45.07 21.82,44.42 22.73,44.42 23.38,45.07 24.52,45.07 25.17,44.42 26.09,44.42 26.73,45.07 27.88,45.07 28.52,44.42 29.44,44.42 30.09,45.07 34.29,45.07 36.51,42.85 41.97,42.85 42.03,42.91 U1.12 42.65,42.91
IN_D1P_R: length 8.2
  TOP w0.127: R198.1 17.39,45.07 16.56,45.07 16.04,44.55 15.86,44.55 15.75,44.66 U19.7 U19.4 14.02,44.66 13.91,44.55 13.34,44.55 v1(13.21,44.68)
  BOTTOM w0.127: P1.4 11.76,44.91 12.12,44.55 13.08,44.55 v1(13.21,44.68)
IN_D2N: length 25.9
  TOP w0.127: R197.2 18.73,47.33 35.06,47.33 38.63,43.77 41.97,43.77 42.03,43.71 U1.10 42.65,43.71
IN_D2N_R: length 9.2
  TOP w0.127: v1(13.21,45.64) 13.34,45.77 13.91,45.77 14.02,45.66 U19.2 U19.9 15.75,45.66 15.86,45.77 16.16,45.77 16.45,46.06 16.45,47.16 16.62,47.33 17.39,47.33 R197.1
  BOTTOM w0.127: P1.3 11.76,45.41 12.12,45.77 13.08,45.77 v1(13.21,45.64)
IN_D2P: length 25.9
  TOP w0.127: R196.2 18.73,47.61 35.18,47.61 38.74,44.05 41.97,44.05 42.03,44.11 U1.9 42.65,44.11
IN_D2P_R: length 9.2
  TOP w0.127: R196.1 17.39,47.61 16.51,47.61 16.17,47.27 16.17,46.18 16.04,46.05 15.86,46.05 15.75,46.16 U19.10 U19.1 14.02,46.16 13.91,46.05 13.34,46.05 v1(13.21,46.18)
  BOTTOM w0.127: P1.1 11.76,46.41 12.12,46.05 13.08,46.05 v1(13.21,46.18)
LINEAR_EN: length 68.3
  TOP w0.203: v1(44.02,46.1) 44.02,45.62 44.25,45.39 U1.5 44.25,44.71
  BOTTOM w0.203: JMP13.4 84.56,19.2 86.03,20.68 86.03,23.24 85.24,24.03 75.9,24.03 73.05,26.87 73.05,36.86 65.13,44.78 54.36,44.78 50.45,48.69 45.41,48.69 44.02,47.3 v1(44.02,46.1)
LV_SCL_SRC: length 30.6
  TOP w0.203: 44.25,39.11 U1.24 44.25,37.13 40.22,33.1 40.22,28.11 TP22.1 41.94,24.22 v1(43.87,24.22)
  BOTTOM w0.203: R168.1 49.71,25.93 47.99,24.22 v1(43.87,24.22)
LV_SDA_SRC: length 17.9
  TOP w0.203: 44.65,39.11 U1.25 44.65,34.62 42.91,32.88 42.91,30.93 TP23.1
  BOTTOM w0.203: TP23.1 48.44,28.65 R169.1
MODE: length 46.5
  TOP w0.203: v1(37.39,31.29) v1(37.39,34.52) ; 42.65,40.91 U1.17 v1(40.74,40.91)
  BOTTOM w0.203: v1(40.74,40.91) 38.75,40.91 37.39,39.55 v1(37.39,34.52) ; v1(37.39,31.29) 36.65,30.56 36.65,13.92 38.18,12.4 42.44,12.4 44.2,10.64 44.2,8.41 42.62,6.83 JMP4.4
OUT_CLKN: length 19
  TOP w0.127: R190.1 63.64,37.63 61.84,37.63 60.45,39.01 49.44,39.01 48.28,40.17 46.93,40.17 46.87,40.11 U1.30 46.25,40.11
OUT_CLKP: length 19
  TOP w0.127: 46.25,40.51 U1.31 46.87,40.51 46.93,40.45 48.4,40.45 49.56,39.29 60.57,39.29 61.95,37.91 63.64,37.91 R189.1
OUT_D0N: length 19.4
  TOP w0.127: 46.25,41.31 U1.33 46.87,41.31 46.93,41.37 49.46,41.37 50.67,40.16 52.83,40.16 54,41.33 58.48,41.33 59.65,40.16 63.66,40.16 R184.1
OUT_D0P: length 19.4
  TOP w0.127: 46.25,41.71 U1.34 46.87,41.71 46.93,41.65 49.58,41.65 50.79,40.44 52.72,40.44 53.88,41.61 58.6,41.61 59.77,40.44 63.63,40.44 R183.1
OUT_D1N: length 19.5
  TOP w0.127: 46.25,42.51 U1.36 46.87,42.51 46.93,42.57 50.06,42.57 51.41,43.92 53.31,43.92 53.9,43.33 58.38,43.33 58.97,43.92 61.2,43.92 62.41,42.71 63.64,42.71 R186.1
OUT_D1P: length 19.5
  TOP w0.127: R185.1 63.64,42.99 62.52,42.99 61.32,44.2 58.85,44.2 58.27,43.61 54.01,43.61 53.43,44.2 51.29,44.2 49.95,42.85 46.93,42.85 46.87,42.91 U1.37 46.25,42.91
OUT_D2N: length 19
  TOP w0.127: R188.1 63.64,45.25 58.7,45.25 58.13,45.82 56,45.82 55.87,45.69 51.36,45.69 49.43,43.77 46.93,43.77 46.87,43.71 U1.39 46.25,43.71
OUT_D2P: length 19
  TOP w0.127: 46.25,44.11 U1.40 46.87,44.11 46.93,44.05 49.32,44.05 51.24,45.97 55.75,45.97 55.88,46.1 58.24,46.1 58.81,45.53 63.64,45.53 R187.1
OUTCLKN_C: length 9.8
  TOP w0.127: P2.12 77.14,38.91 76.78,39.27 76.6,39.27 76.59,39.27 75.98,39.27 75.87,39.16 U21.6 U21.5 74.14,39.16 74.03,39.27 73.81,39.27 72.17,37.63 71.18,37.63 70.92,37.37 L5.2 69.77,37.37 R178.2
OUTCLKP_C: length 9.8
  TOP w0.127: P2.10 77.14,39.91 76.78,39.55 76.48,39.55 76.48,39.55 75.98,39.55 75.87,39.66 U21.7 U21.4 74.14,39.66 74.03,39.55 73.7,39.55 72.06,37.91 71.18,37.91 70.92,38.17 L5.3 69.77,38.17 R177.2
OUTD0N_C: length 9.4
  TOP w0.127: R172.2 69.77,39.91 L7.2 70.92,39.91 71.18,40.17 72.71,40.17 73.31,40.77 74.03,40.77 74.14,40.66 U21.2 U21.9 75.87,40.66 75.98,40.77 76.59,40.77 76.6,40.77 76.78,40.77 77.14,40.41 P2.9
OUTD0P_C: length 9.4
  TOP w0.127: R171.2 69.77,40.71 L7.3 70.92,40.71 71.18,40.45 72.59,40.45 73.19,41.05 74.03,41.05 74.14,41.16 U21.1 U21.10 75.87,41.16 75.98,41.05 76.48,41.05 76.48,41.05 76.78,41.05 77.14,41.41 P2.7
OUTD1N_C: length 9.4
  TOP w0.127: P2.6 77.14,41.91 76.78,42.27 76.6,42.27 76.59,42.26 75.98,42.26 75.87,42.15 U22.6 U22.5 74.14,42.15 74.03,42.26 72.99,42.26 72.54,42.71 71.18,42.71 70.92,42.45 L3.2 69.77,42.45 R174.2
OUTD1P_C: length 9.4
  TOP w0.127: P2.4 77.14,42.91 76.78,42.55 76.48,42.55 76.48,42.54 75.98,42.54 75.87,42.65 U22.7 U22.4 74.14,42.65 74.03,42.54 73.1,42.54 72.66,42.99 71.18,42.99 70.92,43.25 L3.3 69.77,43.25 R173.2
OUTD2N_C: length 9.8
  TOP w0.127: R176.2 69.77,44.99 L4.2 70.92,44.99 71.18,45.25 72.26,45.25 73.03,44.49 73.03,44.47 73.73,43.76 74.03,43.76 74.14,43.65 U22.2 U22.9 75.87,43.65 75.98,43.76 76.53,43.76 76.54,43.77 76.78,43.77 77.14,43.41 P2.3
OUTD2P_C: length 9.8
  TOP w0.127: P2.1 77.14,44.41 76.78,44.05 76.42,44.05 76.42,44.04 75.98,44.04 75.87,44.15 U22.10 U22.1 74.14,44.15 74.03,44.04 73.85,44.04 73.3,44.59 73.3,44.6 72.38,45.53 71.18,45.53 70.92,45.79 L4.3 69.77,45.79 R175.2
PB_MANUAL_RESET: length 16.6
  TOP w0.203: U3.3 73.85,57.53 73.86,57.53 R80.1 74.75,57.02 74.81,57.08 C27.1 75.31,56.06 75.25,56 R79.2 76.27,55.5 78.08,57.31 SW1.3 SW1.4
REG_PG: length 45.8
  TOP w0.203: R80.2 72.96,55.51 71.81,54.36 66.9,54.36 59,62.26 48.72,62.26 45.52,65.45 R83.2 43.99,68.2 42.36,69.83 R81.2 42.36,72.16 43.62,73.42 U4.4
RSTIN: length 4.8
  TOP w0.203: U7.9 20.66,65.47 20.07,64.87 C52.2 17.66,64.87 17.65,64.86 R103.2
SCL_CFG0: length 38
  TOP w0.203: JMP15.3 JMP15.4 23.55,27.51 31.74,35.7 40.63,35.7 43.05,38.12 U1.21 43.05,39.11
SCL_CTL_USB: length 71.7
  TOP w0.203: U7.30 v1(23.11,72.79) ; v1(14.29,71.84) 12.06,69.62 3.89,69.62 0.74,66.47 0.74,34.47 5.16,30.05 JMP15.1
  BOTTOM w0.203: v1(14.29,71.84) 20.1,71.84 21.05,72.79 v1(23.11,72.79) ; R58.2 JMP15.1
SCL_SNK: length 81.1
  TOP w0.127: TP10.1 69.8,31.05 ; 69.8,31.05 69.93,30.92 71.62,30.92 72.92,32.23 72.92,35.65 73.8,36.53 74.78,36.53 R45.1 75.84,36.53 76.1,36.53 76.87,37.3 78.48,37.3 P2.15 ; 69.8,31.05 69.67,30.92 61.2,30.92 60.15,31.98 44.08,31.98 v1(43.96,32.11)
  BOTTOM w0.127: 22.68,34.12 22.56,33.99 20.91,33.99 15.6,39.3 11.89,39.3 11.78,39.41 P1.15 ; 22.68,34.12 TP15.1 ; 22.68,34.12 22.81,33.99 29.28,33.99 31.29,31.98 40.52,31.98 R165.2 41.59,31.99 42.39,31.99 U23.7 42.74,31.99 43.84,31.99 v1(43.96,32.11)
SDA_CFG1: length 47.9
  TOP w0.203: 43.45,39.11 U1.22 43.45,37.91 40.72,35.18 31.88,35.18 25.43,28.73 25.43,19.56 23.75,17.88 14.2,17.88 14.17,17.91 JMP16.4
  BOTTOM w0.203: JMP16.3 JMP16.4
SDA_CTL_USB: length 74.2
  TOP w0.203: U7.29 v1(23.91,72.79)
  BOTTOM w0.203: v1(23.91,72.79) 23.91,62.24 24.94,61.21 24.94,52.93 23.42,51.41 8.66,51.41 5.97,48.72 5.97,21.41 6.93,20.45 R59.2 JMP16.1
SDA_SNK: length 81.2
  TOP w0.127: 69.8,30.52 69.93,30.65 71.73,30.65 73.2,32.12 73.2,35.53 73.91,36.25 74.78,36.25 R46.2 75.84,36.25 76.21,36.25 76.99,37.02 78.48,37.02 P2.16 ; 69.8,30.52 69.67,30.65 61.09,30.65 60.03,31.7 44.08,31.7 v1(43.96,31.57) ; 69.8,30.52 TP11.1
  BOTTOM w0.127: 22.68,33.59 22.81,33.71 29.16,33.71 31.17,31.71 40.52,31.71 R167.2 41.6,31.71 42.37,31.71 U23.6 42.77,31.71 43.82,31.71 v1(43.96,31.57) ; 22.68,33.59 TP16.1 ; 22.68,33.59 22.56,33.71 20.79,33.71 15.49,39.02 11.89,39.02 11.78,38.91 P1.16
SIGDET_OUT: length 40.3
  TOP w0.203: 45.05,39.11 U1.26 45.05,34.16 43.36,32.47 43.36,31.17 44.89,29.64 51.88,29.64 TP20.1 52.15,24.68 45.42,24.68 41.06,29.03 v1(41.06,29.82)
  BOTTOM w0.203: v1(41.06,29.82) R167.1 41.05,30.28 R191.2
SPDIF_IN: length 111.1
  TOP w0.203: v1(81.38,38.33) 80.96,37.91 P2.14
  BOTTOM w0.203: P1.14 8.05,39.91 7.19,40.77 7.19,46.74 8.18,47.73 11.71,47.73 12.93,48.95 23.34,48.95 35.23,60.83 69.27,60.83 72.49,57.61 72.49,54.05 74.93,51.61 78.49,51.61 82.78,47.32 82.78,39.73 v1(81.38,38.33)
TEST1: length 8.4
  TOP w0.203: C61.2 40.64,50.47 45.05,46.06 U1.3 45.05,44.71
TPS3808_CT: length 1.5
  TOP w0.203: C28.1 73.91,62.09 73.85,62.02 U3.4
TXPRE: length 50.1
  TOP w0.203: v1(47.18,39.71) U1.29 46.25,39.71
  BOTTOM w0.203: JMP7.4 54.18,6.83 54.86,7.52 54.86,12.8 54.2,13.46 54.2,23.06 59.59,28.45 59.59,37.66 57.53,39.71 v1(47.18,39.71)
TXSWG: length 63.4
  TOP w0.203: 46.25,43.31 U1.38 v1(47.14,43.31)
  BOTTOM w0.203: v1(47.14,43.31) 57.27,43.31 67.11,33.48 67.11,25.17 65.74,23.8 65.74,15.72 68.07,13.39 75.11,13.39 76.96,11.53 76.96,7.75 76,6.78 JMP9.4
USB_5V: length 4.1
  TOP w0.203: U16.1 v1(16.01,75.62) ; C60.1 v1(15.21,77.39) ; J13.1 v1(15.34,78.13) ; v1(14.36,76.67) C39.1 v1(15.14,75.67)
VIO: length 14.3
  TOP w0.203: v1(41.71,42.11) U1.14 42.65,42.11 ; v1(68.4,58.67) R78.1
  L3 w0.203: J32.1 22.68,27.17 ; J32.1 22.68,24.8 ; J32.1 21.49,25.98 ; J32.1 23.87,25.98
  BOTTOM w0.203: R152.2 v1(26.63,19.06) ; v1(41.71,42.11) 41.46,41.86 C63.1 ; U23.1 v1(46.97,33.87) ; R180.2 v1(16.68,20.45) ; R206.1 v1(11.87,13) ; R58.1 v1(7.45,30.66) ; R59.1 v1(8.1,21.97) ; R204.2 v1(16.02,30.74) ; R205.1 v1(7.3,25.57) ; R170.1 v1(51,16.96) ; R150.2 v1(28.54,30.52)
X1: length 8.8
  TOP w0.203: U7.27 25.51,75.45 24.51,76.45 24.51,78.91 25.52,79.92 Y1.3 25.97,80.47 C51.1
X2: length 6.3
  TOP w0.203: U7.26 26.31,75.46 27.32,76.46 Y1.1 27.32,77.82 28.03,78.53 28.13,78.53 28.14,78.54 C50.1
N16782838: length 3.1
  TOP w0.203: R77.2 R78.2 70.66,58.67 70.69,58.64 U3.1
N16887406: length 2.1
  TOP w0.203: R102.2 24.34,64.11 24.23,64.11 23.91,64.43 U7.12
